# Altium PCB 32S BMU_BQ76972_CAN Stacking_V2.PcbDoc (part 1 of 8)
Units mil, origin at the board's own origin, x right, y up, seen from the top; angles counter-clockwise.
Board outline 7319.29 x 5216.54 mil, 4 copper layers (Top Layer, Layer 1, Layer 2, Bottom Layer), stack 73.068 mil thick; 811 components, 524 nets, 2320 pads, 2669 vias.
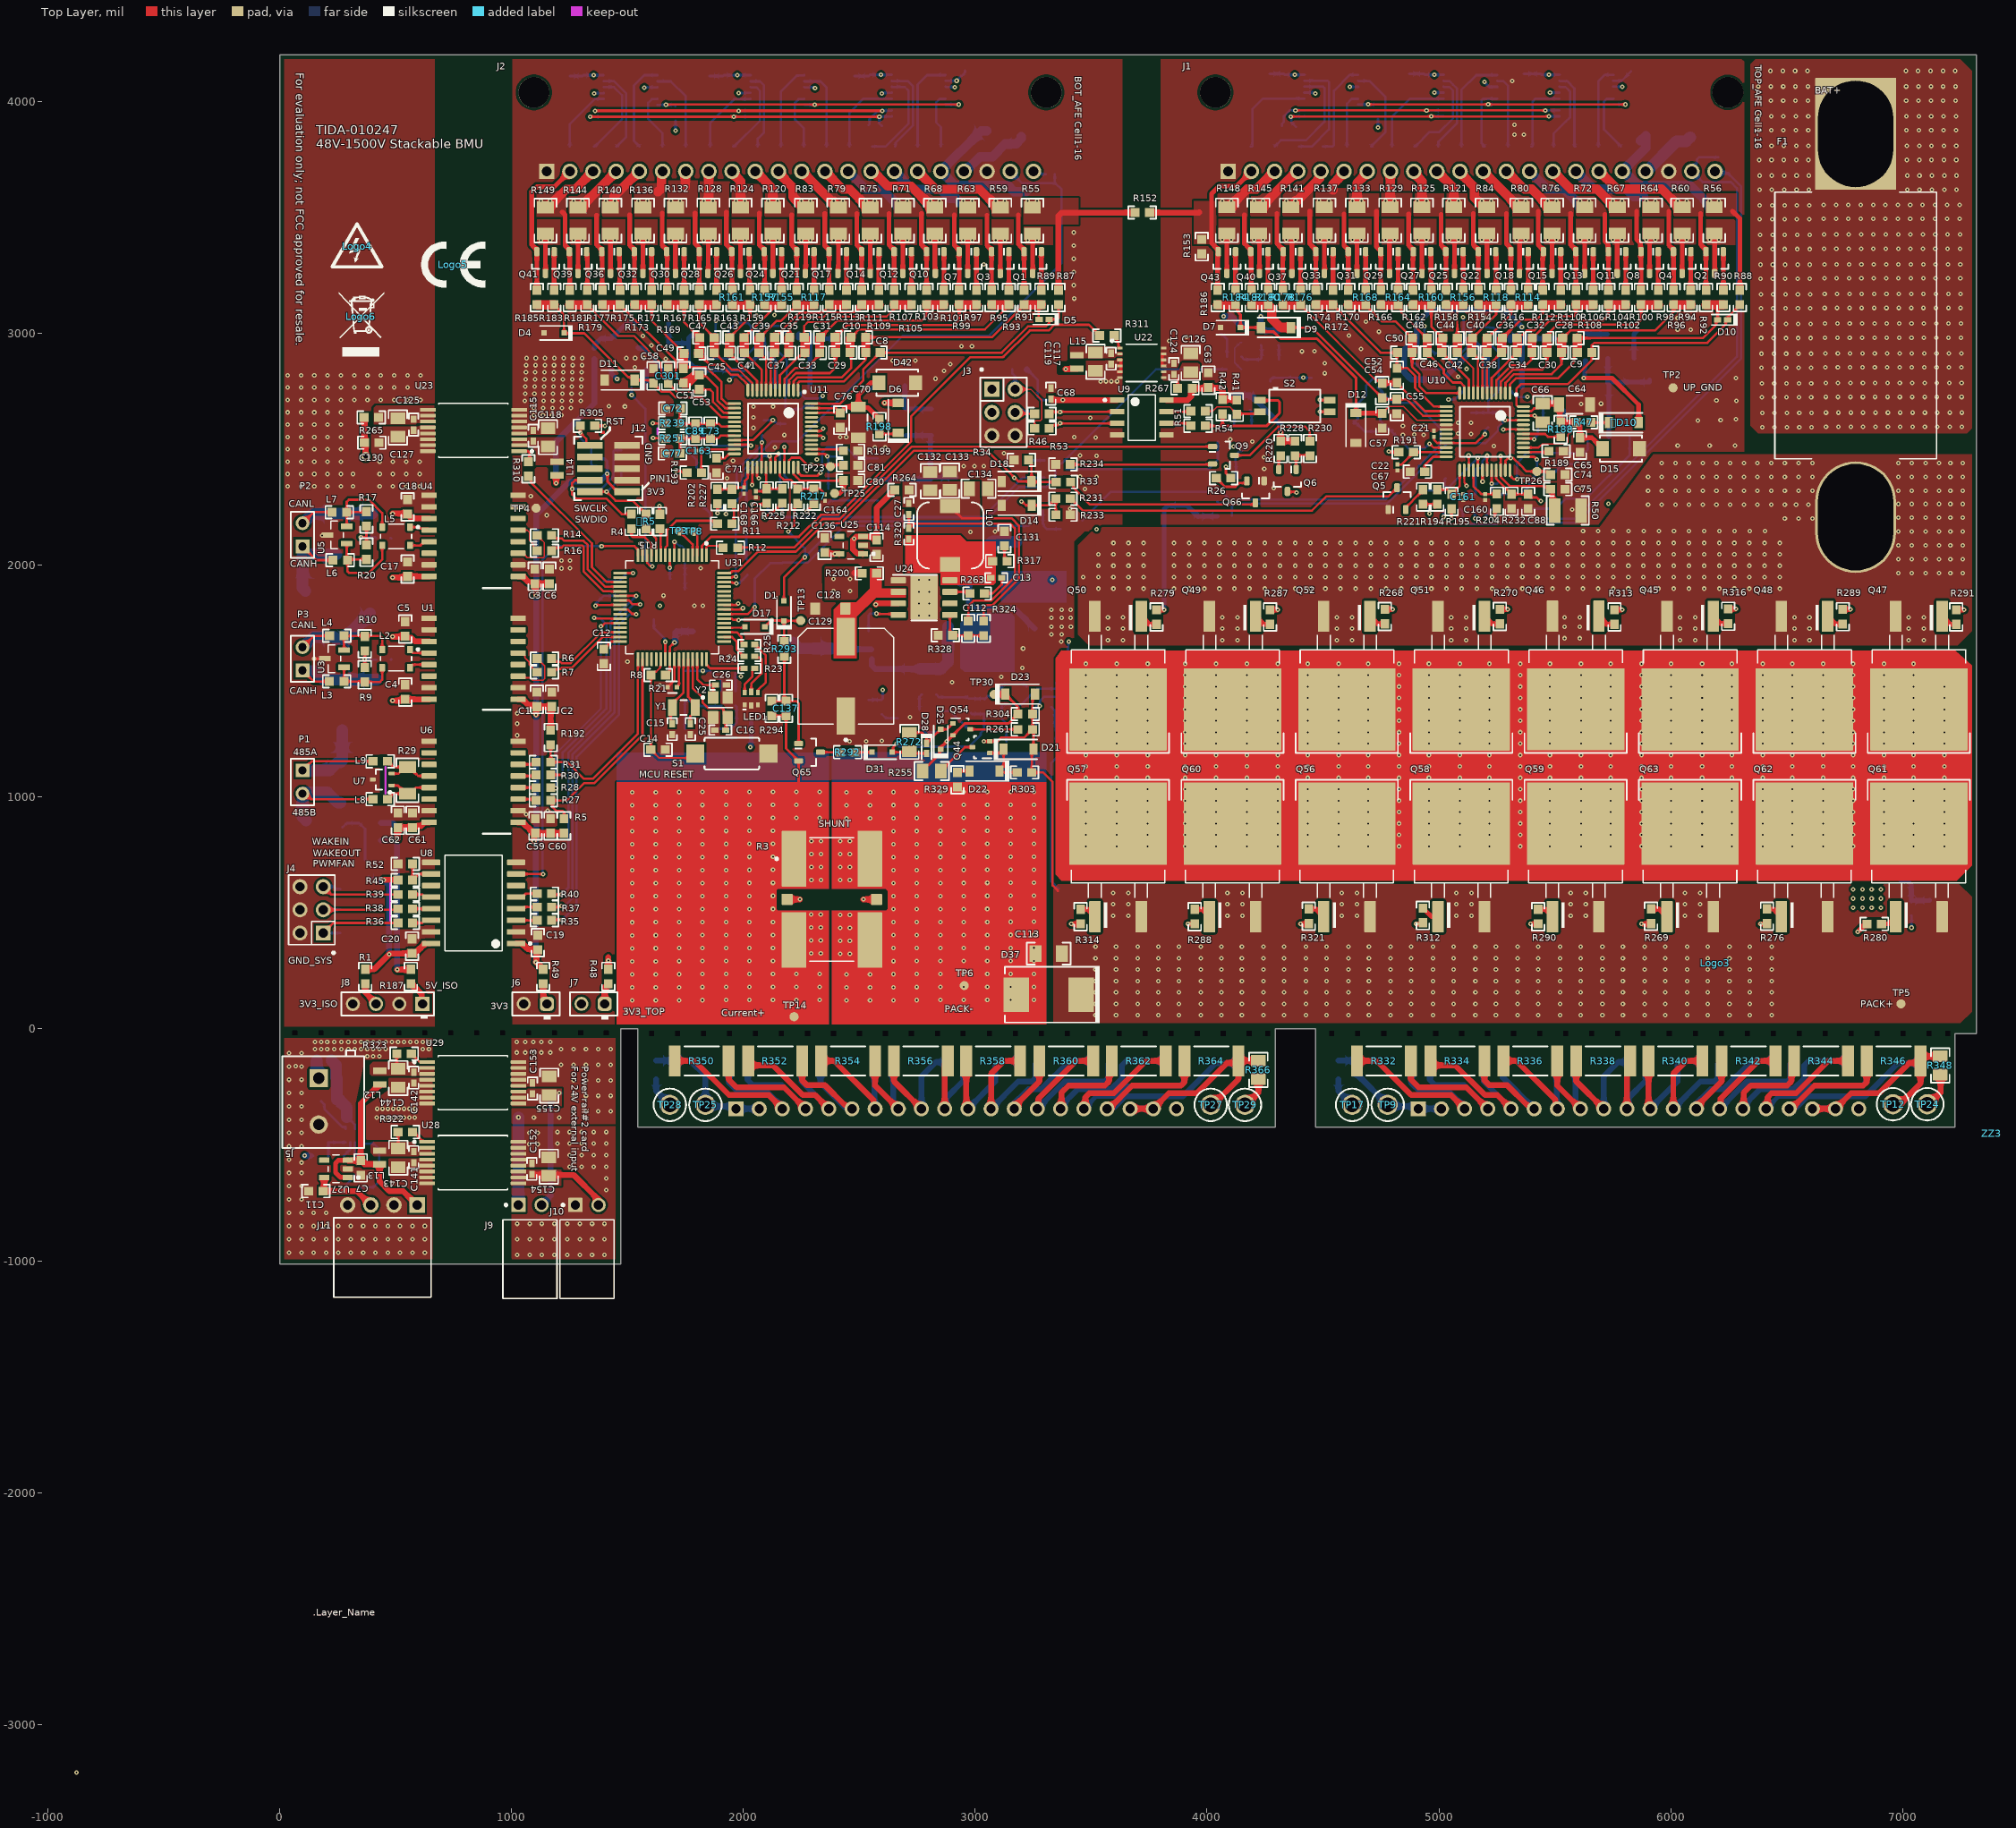
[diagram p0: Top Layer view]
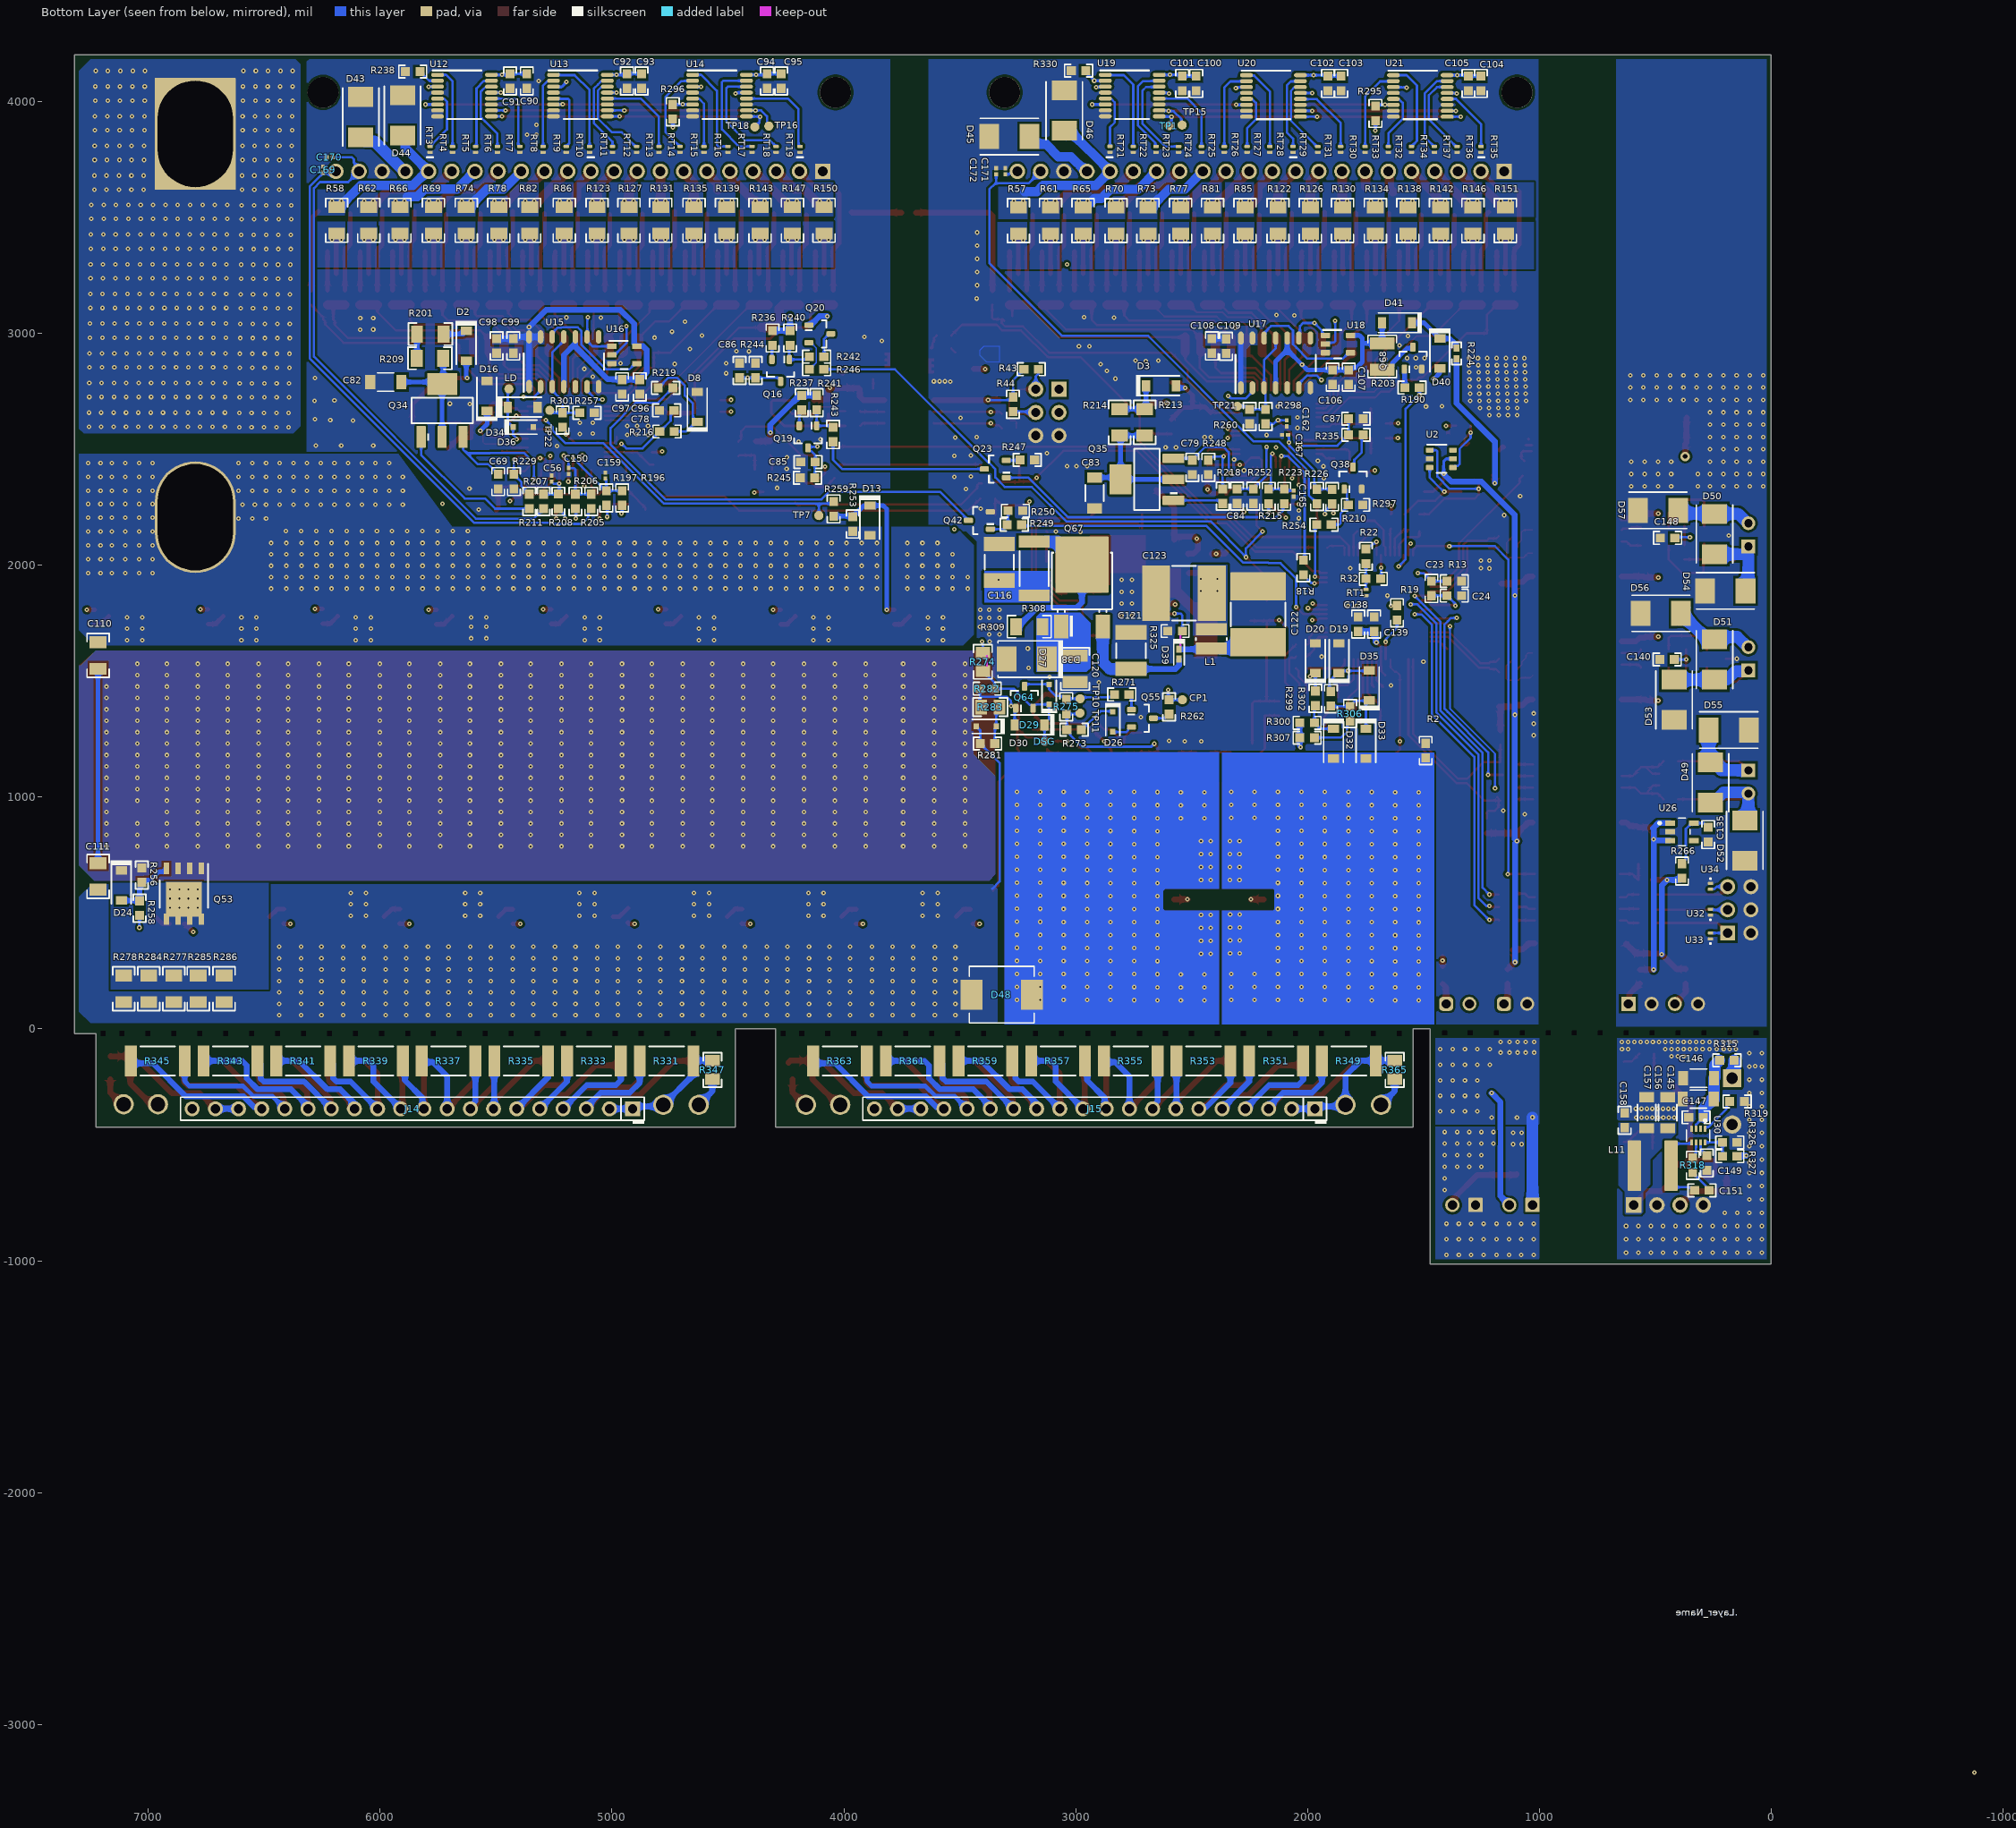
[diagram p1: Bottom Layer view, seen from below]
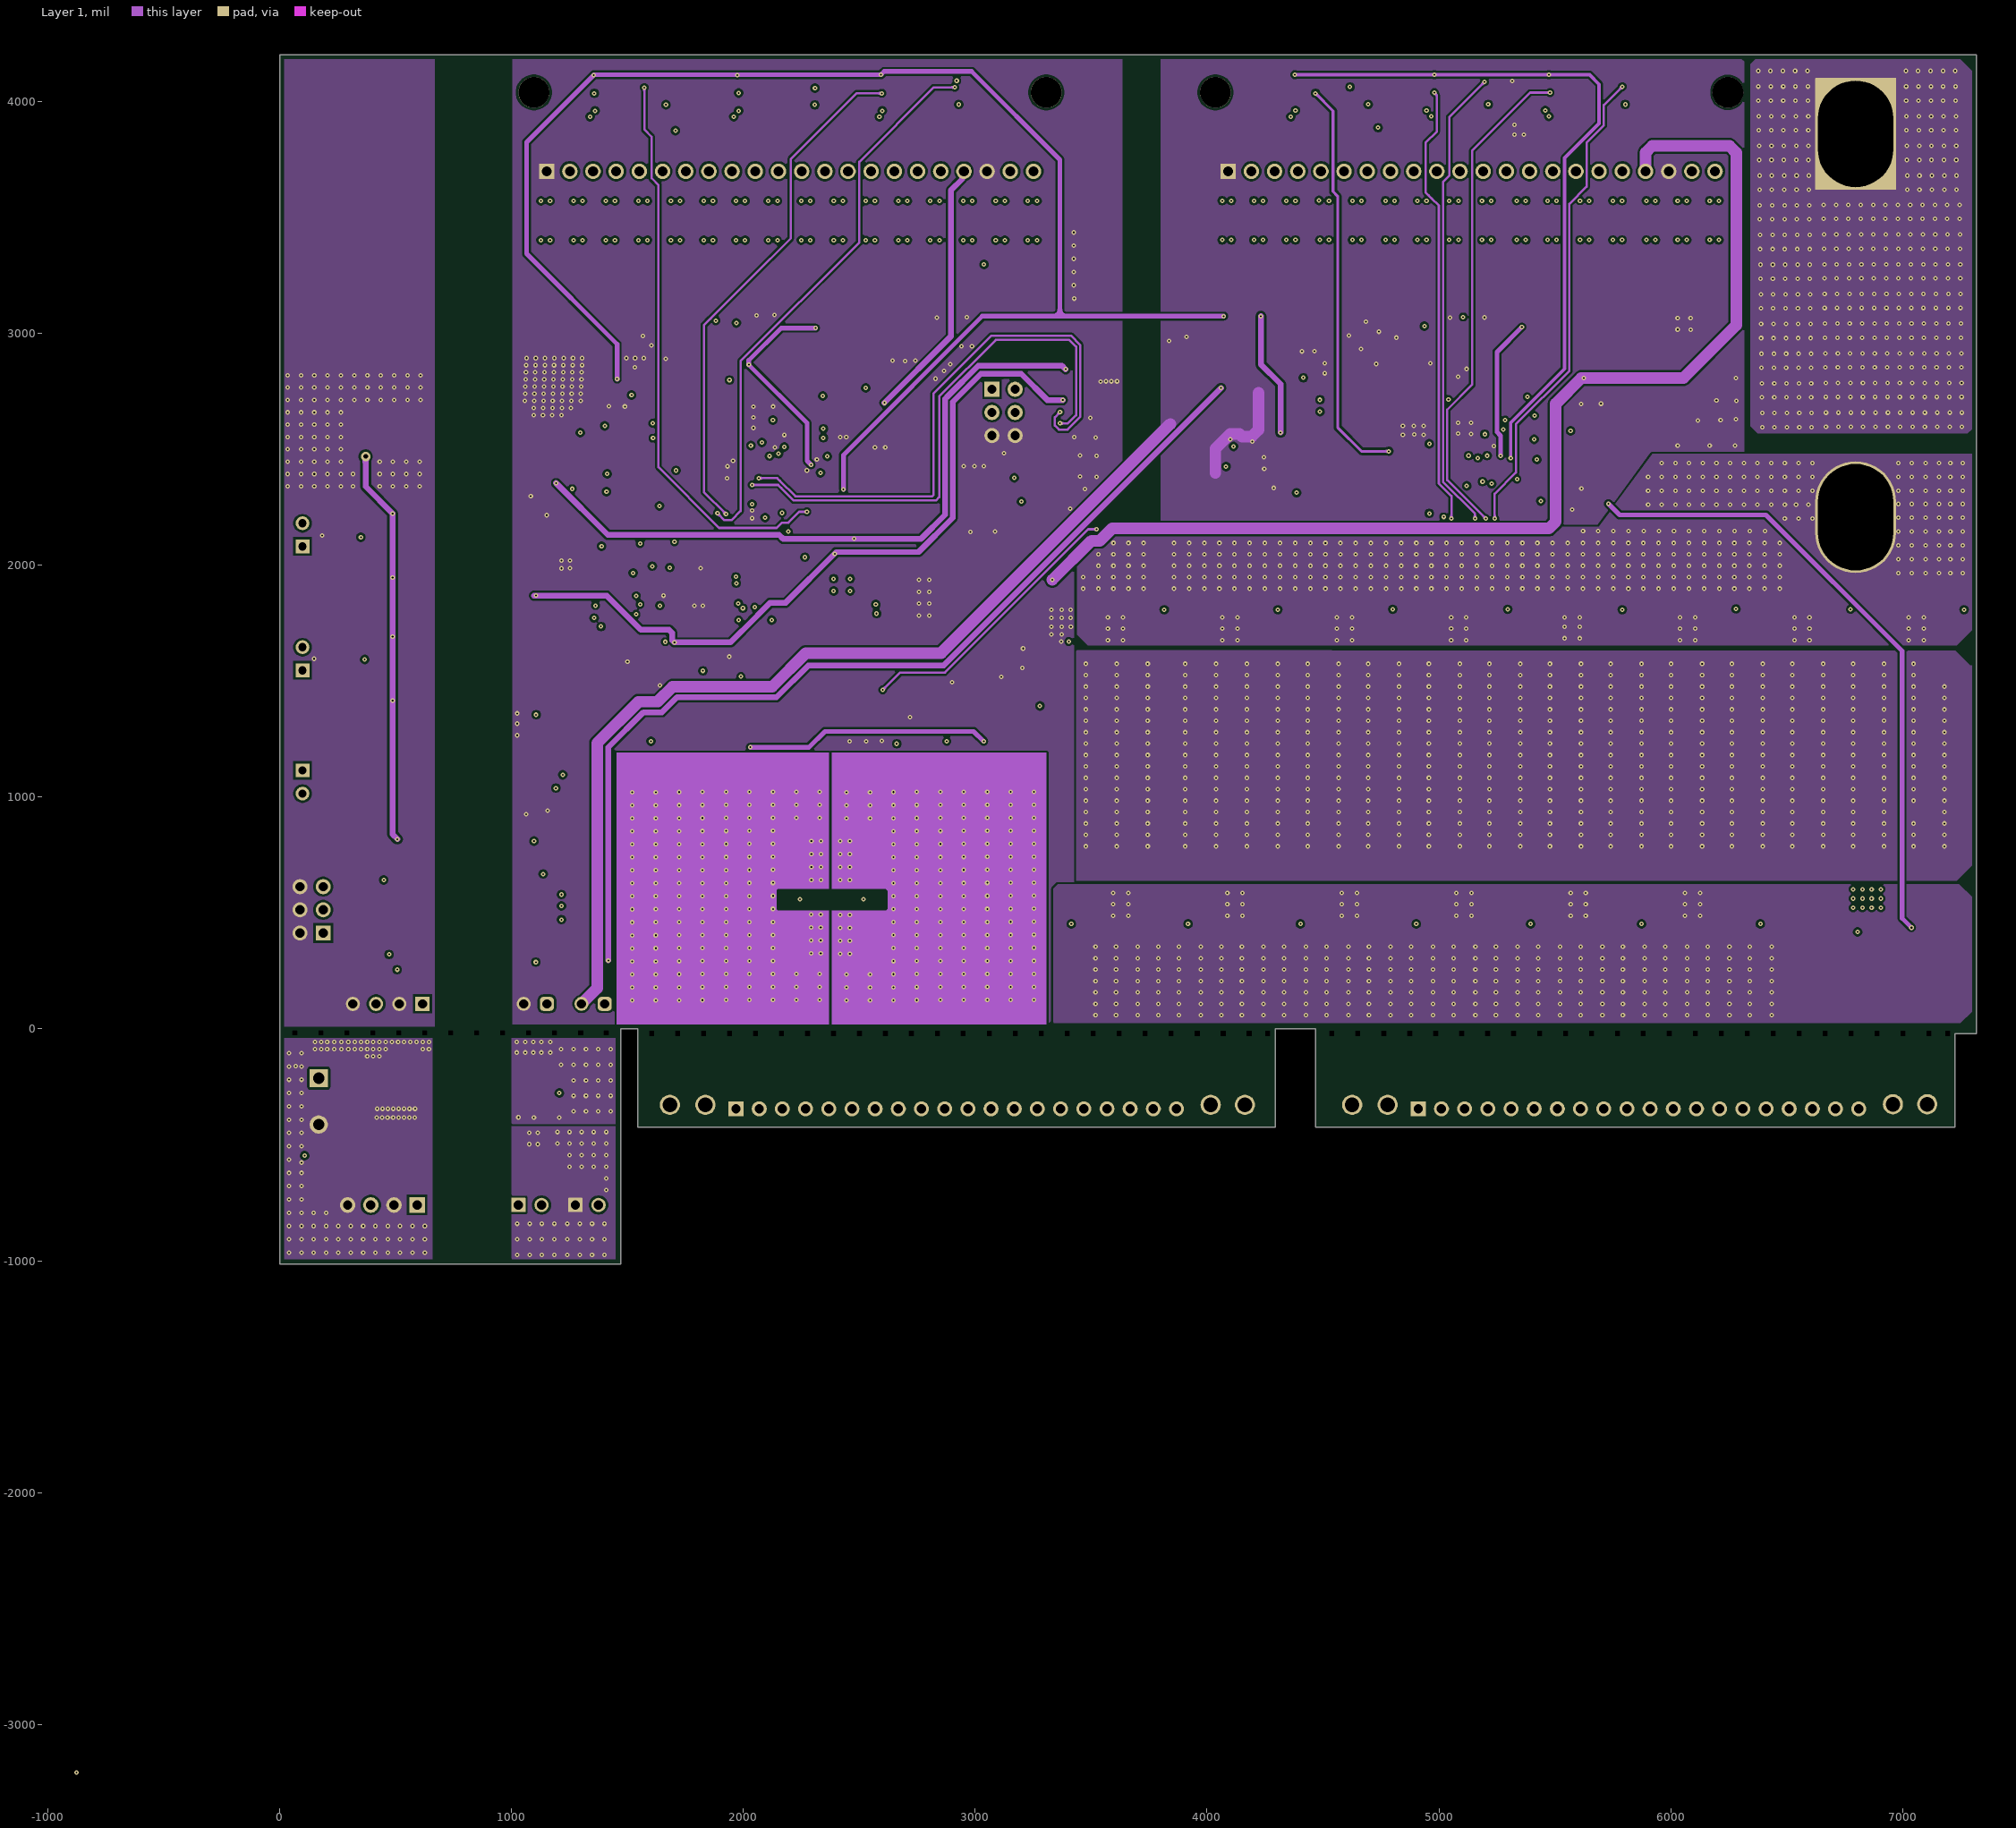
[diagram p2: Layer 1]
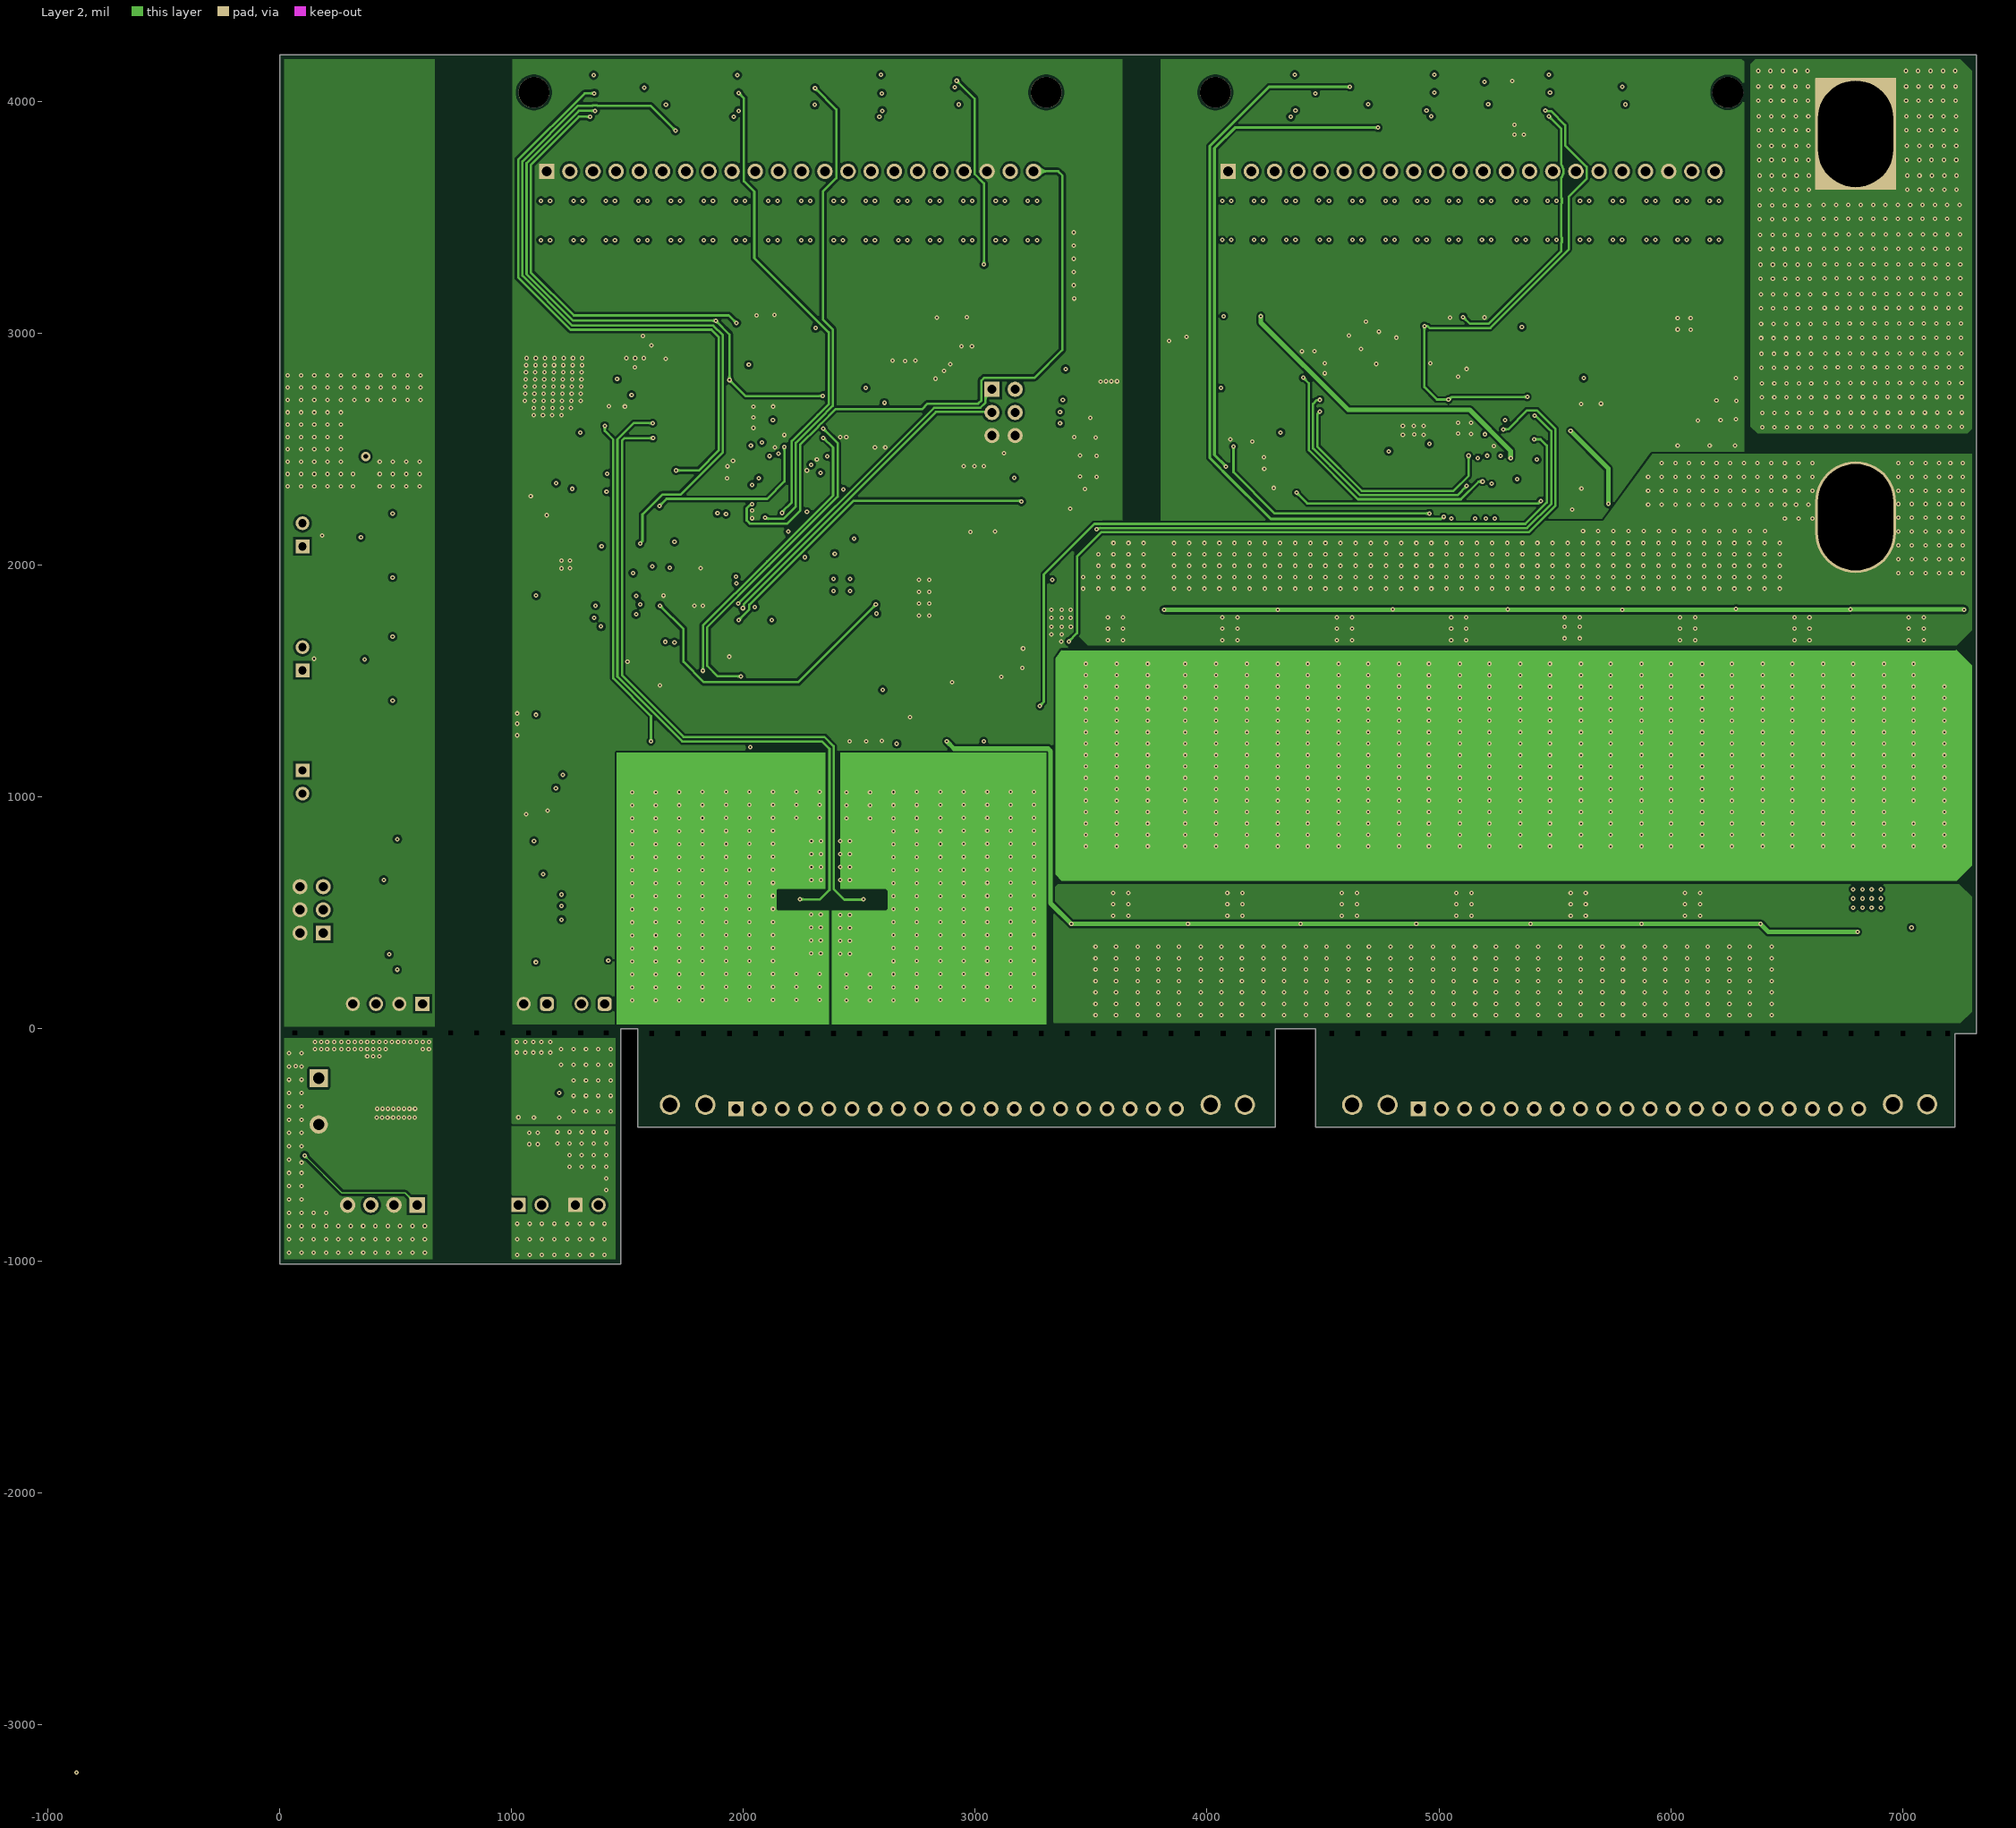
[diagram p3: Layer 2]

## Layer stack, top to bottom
Top Solder: solder mask 0.4, Solder Resist, Dk 3.5
Top Layer: signal copper 2.756
Dielectric 1: prepreg 2.8, PP-006, Dk 4.1
Layer 1: signal copper 1.378
Dielectric1: core 59.2, FR-4 High Tg, Dk 4.8
Layer 2: signal copper 1.378
Dielectric 2: prepreg 2.8, PP-006, Dk 4.1
Bottom Layer: signal copper 2.756
Bottom Solder: solder mask 0.4, Solder Resist, Dk 3.5

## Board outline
0,-1013.78 1470.69,-1013.78 1470.69,0 1545.28,0 1545.28,-423.54 4293.61,-423.54 4293.61,0 4468.5,0 4468.5,-423.54 7226.68,-423.54 7226.68,-19.68 7319.29,-19.68 7319.29,4202.76 0,4202.76

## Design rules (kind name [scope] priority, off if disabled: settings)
AcuteAngle [All] p1: minimum=4.50000000000000E+0001 checktracksonly=FALSE
AssemblyTestPointUsage [All] p1: valid=2
BoardOutlineClearance [Not InComponent('J1_2') AND  Not InComponent('J1_1')] p1: gap=0 ignorepadtopadclearanceinfootprint=FALSE except(20: Arc-OutlineEdge Arc-CavityEdge Arc-CutoutEdge Arc-SplitBarrior Arc-SplitContinuation Fill-OutlineEdge Fill-CavityEdge Fill-CutoutEdge Fill-SplitBarrior Fill-SplitContinuation Poly-OutlineEdge Poly-CavityEdge Poly-CutoutEdge Poly-SplitBarrior Poly-SplitContinuation Region-OutlineEdge Region-CavityEdge Region-CutoutEdge Region-SplitBarrior Region-SplitContinuation)
Clearance Clearance_BoardEdge_MountingHoles [OnCopper and InComponentClass('Mounting Holes') vs IsKeepOut] p1: gap=40 ignorepadtopadclearanceinfootprint=FALSE except(0: Arc-Hole Track-Hole SMDPad-Hole THPad-Hole Via-Hole Fill-Hole Poly-Hole Region-Hole Text-Hole)
Clearance Clearance_BoardEdge_Poly [OnCopper and InPoly vs IsKeepOut] p2: gap=20 ignorepadtopadclearanceinfootprint=FALSE except(0: Arc-Hole Track-Hole SMDPad-Hole THPad-Hole Via-Hole Fill-Hole Poly-Hole Region-Hole Text-Hole)
Clearance Clearance_BoardEdge [OnCopper and Not InComponentClass('Logo') and not InComponentClass('FiducialMark') and not InRegion(1000,500,4000,800) and Not IsKeepout vs IsKeepOut] p3: gap=5 ignorepadtopadclearanceinfootprint=FALSE except(0: Arc-Hole Track-Hole SMDPad-Hole THPad-Hole Via-Hole Fill-Hole Poly-Hole Region-Hole Text-Hole)
Clearance Clearance_Poly [InPolygon] p4: gap=10 ignorepadtopadclearanceinfootprint=FALSE except(0: Arc-Hole Track-Hole SMDPad-Hole THPad-Hole Via-Hole Fill-Hole Poly-Hole Region-Hole Text-Hole)
Clearance [All] p5: gap=8 ignorepadtopadclearanceinfootprint=FALSE except(0: Arc-Hole Track-Hole SMDPad-Hole THPad-Hole Via-Hole Fill-Hole Poly-Hole Region-Hole Text-Hole; 7: SMDPad-SMDPad)
ComponentClearance ComponentClearance_Logo [All] p1: gap=10 collisioncheckmode=3 verticalgap=10 showdistances=TRUE
ComponentClearance ComponentClearance_ScrewToNut [(HasFootprint('NY PMS 440 0025 PH')) vs (HasFootprint('Keystone_1902C'))] p2: gap=5 collisioncheckmode=3 verticalgap=10 showdistances=FALSE
ComponentClearance ComponentClearance_MountingHoles [InComponentClass('Mounting Holes')] p3: gap=10 collisioncheckmode=3 verticalgap=100000 showdistances=FALSE
ComponentClearance ComponentClearance_SmallPassives [HasFootprint('0201*') or HasFootprint('0402*') or HasFootprint('0508') or HasFootprint('0603*') or HasFootprint('0612') or HasFootprint('0805*') or HasFootprint('0815*') or HasFootprint('0830*') or HasFootprint('1206*') or HasFootprint('1210*') or HasFootprint('1808*') or HasFootprint('1812*') or HasFootprint('1825*') or HasFootprint('2010*') or HasFootprint('2220*') or HasFootprint('2225*') or HasFootprint('2512*') or HasFootprint('2728*') or HasFootprint('3518*') vs HasFootprint('0201*') or HasFootprint('0402*') or HasFootprint('0508') or HasFootprint('0603*') or HasFootprint('0612') or HasFootprint('0805*') or HasFootprint('0815*') or HasFootprint('0830*') or HasFootprint('1206*') or HasFootprint('1210*') or HasFootprint('1808*') or HasFootprint('1812*') or HasFootprint('1825*') or HasFootprint('2010*') or HasFootprint('2220*') or HasFootprint('2225*') or HasFootprint('2512*') or HasFootprint('2728*') or HasFootprint('3518*')] p4: gap=10 collisioncheckmode=3 verticalgap=10 showdistances=FALSE
ComponentClearance ComponentClearance_THtoSMT [IsThruComponent vs IsSMTComponent] p5: gap=10 collisioncheckmode=3 verticalgap=100000 showdistances=FALSE
ComponentClearance ComponentClearance_THtoTH [IsThruComponent vs IsThruComponent] p6: gap=10 collisioncheckmode=3 verticalgap=100000 showdistances=FALSE
ComponentClearance [All] p7: gap=10 collisioncheckmode=3 verticalgap=10 showdistances=FALSE
DiffPairsRouting [All] p1: maxlimit=100 minlimit=10 mostfreqgap=10 toplayer_minwidth=15 toplayer_maxwidth=15 toplayer_prefwidth=15 midlayer1_minwidth=15 midlayer1_maxwidth=15 midlayer1_prefwidth=15 midlayer2_minwidth=15 midlayer2_maxwidth=15 midlayer2_prefwidth=15 bottomlayer_minwidth=15 bottomlayer_maxwidth=15 bottomlayer_prefwidth=15 maxuncoupledlength=1000
FabricationTestPointUsage TestPointUsage [All] p1: valid=2 allowmultiple=FALSE
FabricationTestpoint Testpoint [All] p1: side=3 testpointundercomponent=TRUE minsize=40 maxsize=100 preferedsize=60 minholesize=0 maxholesize=40 preferedholesize=32 testpointgrid=1 allowsidetop=TRUE allowsidebottom=TRUE usegrid=TRUE gridtolerance=0.01
FanoutControl Fanout_LCC [IsLCC] p1: bgadir=Out bgaviamode=Centered fanoutstyle=Auto fanoutdirection=Alternating viagrid=1 // Fanout_LCC (Default Rule)
FanoutControl Fanout_BGA [IsBGA] p2: bgadir=Out bgaviamode=Centered fanoutstyle=Auto fanoutdirection=Alternating viagrid=1 // Fanout_BGA (Default Rule)
FanoutControl Fanout_Default [All] p4: bgadir=Out bgaviamode=Centered fanoutstyle=Auto fanoutdirection=Alternating viagrid=1 // Fanout_Default (Default Rule)
FanoutControl Fanout_Small [(CompPinCount < 5)] p5: bgadir=Out bgaviamode=Centered fanoutstyle=Auto fanoutdirection=OutThenIn viagrid=1 // Fanout_Small (Default Rule)
HoleSize [Not InComponent('F1')] p1: absolutevalues=TRUE maxlimit=251 minlimit=6 maxpercent=80.000 minpercent=20.000
MinimumAnnularRing [All] p1: minimumring=3
MinimumSolderMaskSliver MinimumSolderMaskSliver_Logo [InComponentClass('Logo') vs InComponentClass('Logo')] p1: minsoldermaskwidth=0.7
MinimumSolderMaskSliver [All] p2: minsoldermaskwidth=0
PlaneConnect [All] p1: planeconnectstyle=Direct reliefexpansion=10 reliefentries=4 reliefconductorwidth=10 reliefairgap=10
PolygonConnect [All] p1: connectstyle=Direct reliefconductorwidth=10 reliefentries=4 polygonreliefangle="90 Angle" airgapwidth=10
RoutingCorners [All] p1: cornerstyle=45-Degree minsetback=10 maxsetback=100
RoutingVias [All] p1: holewidth=16 width=34 viastyle="Through Hole" minholewidth=0 minwidth=0 maxholewidth=40 maxwidth=65
SMDToCorner [All] p1: distance=0
SilkToBoardRegionClearance [Not ((IsComment or IsDesignator) And (Hide <> 'False')) and not InRegion(1000,500,4000,800)] p1:
SilkToSilkClearance [All] p1: silktosilkclearance=0
SilkToSolderMaskClearance SilkscreenOverComponentPads [IsPad] p1: minsilkscreentomaskgap=0 clearancetoexposedcopper=TRUE
SolderMaskExpansion [All] p1: expansion=3 istentingtop=FALSE
Width [All] p1: maxlimit=100 minlimit=6 preferedwidth=10 checkconnectedcopper=TRUE
14 further rules are at their usual default settings.

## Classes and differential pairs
component class S8: J14 J15 R331 R332 R333 R334 R335 R336 R337 R338 R339 R340 R341 R342 R343 R344 R345 R346 R347 R348 R349 R350 R351 R352 R353 R354 R355 R356 R357 R358 R359 R360 R361 R362 R363 R364 R365 R366 TP9 TP12 TP17 TP24 TP25 TP27 TP28 TP29
component class U_EVM_Hardware: !PCB1 Logo3 Logo4 Logo5 Logo6 ZZ1 ZZ2 ZZ3
component class S6: C7 C11 C141 C142 C143 C144 C145 C146 C147 C149 C151 C152 C153 C154 C155 C156 C157 C158 J9 J10 J11 L11 L12 L13 R315 R318 R319 R322 R323 R326 R327 U27 U28 U29 U30
component class S5: C13 C27 C112 C114 C115 C116 C117 C118 C119 C120 C121 C122 C123 C124 C125 C126 C127 C128 C129 C130 C131 C132 C133 C134 C135 C136 D38 D39 J6 J7 J8 L1 L10 L14 L15 Q67 R1 R48 R49 R187 R200 R263 R264 R265 R266 R267 R308 R309 R310 R311 R317 R320 R324 R325 R328 U22 U23 U24 U25 U26
component class S4: C90 C91 C92 C93 C94 C95 C96 C97 C98 C99 C100 C101 C102 C103 C104 C105 C106 C107 C108 C109 R238 R257 R260 R295 R296 R298 R301 R330 RT3 RT4 RT5 RT6 RT7 RT8 RT9 RT10 RT11 RT12 RT13 RT14 RT15 RT16 RT17 RT18 RT19 RT21 RT22 RT23 RT24 RT25 RT26 RT27 RT28 RT29 RT30 RT31 RT32 RT33 RT34 RT35 RT36 RT37 TP1 TP15 TP16 TP18 TP21 TP22 TP23 TP25 TP26 U12 U13 U14 U15 U16 U17 U18 U19 U20 U21
component class S3: C1 C2 C3 C4 C5 C6 C12 C14 C15 C16 C17 C18 C19 C20 C23 C24 C25 C26 C59 C60 C61 C62 C63 C68 C138 C139 C140 C148 D17 D18 D49 D50 D51 D52 D53 D54 D55 D56 D57 J3 J12 L2 L3 L4 L5 L6 L7 L8 L9 LED1 Q66 R4 R5 R6 R7 R8 R9 R10 R11 R12 R13 R14 R15 R16 R17 R18 R19 R20 R21 R22 R23 R24 R25 R26 R27 R28 R29 R30 R31 R32 R33 R34 R35 R36 R37 R38 R39 R40 R41 R42 R43 R44 R45 R46 R51 R52 R53 R54 R192 R305 RT1 S1 S2 TP3 TP8 U1 U2 U3 U4 U5 U6 U7 U8 U9 U31 U32 U33 U34 Y1 Y2
component class S2: C110 C111 C113 C137 CP1 D13 D16 D19 D20 D21 D22 D23 D24 D25 D26 D27 D28 D29 D30 D31 D32 D33 D34 D35 D36 D37 D48 DSG F1 LD Q44 Q45 Q46 Q47 Q48 Q49 Q50 Q51 Q52 Q53 Q54 Q55 Q56 Q57 Q58 Q59 Q60 Q61 Q62 Q63 Q64 Q65 R253 R255 R256 R258 R259 R261 R262 R268 R269 R270 R271 R272 R273 R274 R275 R276 R277 R278 R279 R280 R281 R282 R283 R284 R285 R286 R287 R288 R289 R290 R291 R292 R293 R294 R299 R300 R302 R303 R304 R306 R307 R312 R313 R314 R316 R321 R329 TP5 TP6 TP7 TP10 TP11 TP13 TP14 TP30
component class S1: C8 C9 C10 C21 C22 C28 C29 C30 C31 C32 C33 C34 C35 C36 C37 C38 C39 C40 C41 C42 C43 C44 C45 C46 C47 C48 C49 C50 C51 C52 C53 C54 C55 C56 C57 C58 C64 C65 C66 C67 C69 C70 C71 C72 C73 C74 C75 C76 C77 C78 C79 C80 C81 C82 C83 C84 C85 C86 C87 C88 C89 C150 C159 C160 C161 C162 C163 C164 C165 C166 C167 C168 C301 D2 D3 D4 D5 D6 D7 D8 D9 D10 D11 D12 D14 D15 D40 D41 D42 Q1 Q2 Q3 Q4 Q5 Q6 Q7 Q8 Q9 Q10 Q11 Q12 Q13 Q14 Q15 Q16 Q17 Q18 Q19 Q20 Q21 Q22 Q23 Q24 Q25 Q26 Q27 Q28 Q29 Q30 Q31 Q32 Q33 Q34 Q35 Q36 Q37 Q38 Q39 Q40 Q41 Q42 Q43 Q68 R47 R50 R55 R56 R57 R58 R59 R60 R61 R62 R63 R64 R65 R66 R67 R68 R69 R70 R71 R72 R73 R74 R75 R76 R77 R78 R79 R80 R81 R82 R83 R84 R85 R86 R87 R88 R89 R90 R91 R92 R93 R94 R95 R96 R97 R98 R99 R100 R101 R102 R103 R104 R105 R106 R107 R108 R109 R110 R111 R112 R113 R114 R115 R116 R117 R118 R119 R120 R121 R122 R123 R124 R125 R126 R127 R128 R129 R130 R131 R132 R133 R134 R135 R136 R137 R138 R139 R140 R141 R142 R143 R144 R145 R146 R147 R148 R149 R150 R151 R152 R153 R154 R155 R156 R157 R158 R159 R160 R161 R162 R163 R164 R165 R166 R167 R168 R169 R170 R171 R172 R173 R174 R175 R176 R177 R178 R179 R180 R181 R182 R183 R184 R185 R186 R188 R189 R190 R191 R193 R194 R195 R196 R197 R198 R199 R201 R202 R203 R204 R205 R206 R207 R208 R209 R210 R211 R212 R213 R214 R215 R216 R217 R218 R219 R220 R221 R222 R223 R224 R225 R226 R227 R228 R229 R230 R231 R232 R233 R234 R235 R236 R237 R239 R240 R241 R242 R243 R244 R245 R246 R247 R248 R249 R250 R251 R252 R254 R297 TP2 TP4 U10 U11
component class "High Level Sheet": C169 C170 C171 C172 D1 D43 D44 D45 D46 J1 J2 J4 J5 P1 P2 P3 R2 R3

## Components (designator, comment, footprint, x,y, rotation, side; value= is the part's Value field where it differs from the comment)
D10 "BAT46W-7-F" SOD-123 5797.43,2615.29 r0 top value=100V (schematic designator D10)
R5 "CRCW0603100RFKEA" 0603 1580.52,2189.14 r270 top value=100 (schematic designator R5)
C1 "GRM188R61C104KA01D" 0603 1109.36,1421.63 r90 top value=0.1uF
C2 "CC0603MRX5R7BB105" 0603 1173.92,1421.63 r90 top value=1uF
C3 "EMK107BBJ106MA-T" 0603 1100.5,1952.08 r90 top value=0.1uF
C4 "GRM188R61C104KA01D" 0603 541.45,1453.12 r90 top value=0.1uF
C5 "GRM188R61C104KA01D" 0603 541.45,1725.45 r90 top value=0.1uF
C6 "EMK107BBJ106MA-T" 0603 1163.49,1952.08 r90 top value=1uF
C7 "GCM188R71C105KA64D" 0603 349.65,-599.42 r270 top value=1uF
C8 "GRM188R71H104KA93D" 0603 2558.95,2917.56 r180 top value=0.1uF
C9 "GRM188R71H104KA93D" 0603 5628.53,2917.56 r180 top value=0.1uF
C10 "GRM188R71H104KA93D" 0603 2496.13,2983.7 r180 top value=0.1uF
C11 "GRM188Z71C225KE43" 0603 156.29,-699.33 r180 top value=2.2uF
C12 "GCM188R71C474KA55D" 0603 1398.12,1606.97 r90 top value=0.47uF
C13 "GRM155R71H222KA01D" 0402 3090.77,1945.98 r180 top value=2200pF
C14 "C0603X103K1RACTU" 0603 1631.89,1204.72 r0 top value=0.01uF
C15 "GRM1555C1H220JA01D" 0402 1692.91,1293.31 r90 top value=22pF
C16 "GRM1555C1H220JA01D" 0402 1900.34,1289.37 r180 top value=22pF
C17 "GRM188R61C104KA01D" 0603 551.29,1983.58 r90 top value=0.1uF
C18 "GRM188R61C104KA01D" 0603 551.29,2252.08 r90 top value=0.1uF
C19 "GRM188R61C104KA01D" 0603 1113.26,372.42 r270 top value=0.1uF
C20 "GRM188R61C104KA01D" 0603 570.98,357.34 r270 top value=0.1uF
C21 "GRM033R71C471KA01D" 0201 4979.03,2566.69 r270 top value=470pF
C22 "GRM033R71C471KA01D" 0201 4821.61,2422.08 r90 top value=470pF
C23 "GCM188R71C105KA64J" 0603 1465.57,1900.22 r270 bottom value=1uF
C24 "C1608X5R1E105K080AC" 0603 1367.15,1868.72 r180 bottom value=1uF
C25 "GRM1555C1H220JA01D" 0402 1771.65,1293.31 r90 top value=22pF
C26 "GRM1555C1H220JA01D" 0402 1903,1483.48 r0 top value=22pF
C27 "GRM155R71H152KA01D" 0402 2713.67,2243.2 r270 top value=1500pF
C28 "GRM188R71H104KA93D" 0603 5564.8,2980.12 r180 top value=0.1uF
C29 "GRM188R71H104KA93D" 0603 2428.72,2917.56 r180 top value=0.1uF
C30 "GRM188R71H104KA93D" 0603 5497.53,2917.56 r180 top value=0.1uF
C31 "GRM188R71H104KA93D" 0603 2363.87,2983.7 r180 top value=0.1uF
C32 "GRM188R71H104KA93D" 0603 5434.34,2980.12 r180 top value=0.1uF
C33 "GRM188R71H104KA93D" 0603 2297.35,2916.58 r180 top value=0.1uF
C34 "GRM188R71H104KA93D" 0603 5369.58,2917.56 r180 top value=0.1uF
C35 "GRM188R71H104KA93D" 0603 2230.87,2983.7 r180 top value=0.1uF
C36 "GRM188R71H104KA93D" 0603 5305.4,2980.12 r180 top value=0.1uF
C37 "GRM188R71H104KA93D" 0603 2164.31,2916.58 r180 top value=0.1uF
C38 "GRM188R71H104KA93D" 0603 5239.1,2917.56 r180 top value=0.1uF
C39 "GRM188R71H104KA93D" 0603 2103.28,2983.7 r180 top value=0.1uF
C40 "GRM188R71H104KA93D" 0603 5176.34,2980.12 r180 top value=0.1uF
C41 "GRM188R71H104KA93D" 0603 2036.35,2916.58 r180 top value=0.1uF
C42 "GRM188R71H104KA93D" 0603 5110.57,2917.56 r180 top value=0.1uF
C43 "GRM188R71H104KA93D" 0603 1971.66,2982.71 r180 top value=0.1uF
C44 "GRM188R71H104KA93D" 0603 5048.34,2980.12 r180 top value=0.1uF
C45 "GRM188R71H104KA93D" 0603 1905.12,2916.58 r180 top value=0.1uF
C46 "GRM188R71H104KA93D" 0603 4981.08,2917.56 r180 top value=0.1uF
C47 "GRM188R71H104KA93D" 0603 1842.75,2982.71 r180 top value=0.1uF
C48 "GRM188R71H104KA93D" 0603 4917.86,2980.12 r180 top value=0.1uF
C49 "GRM188R71H104KA93D" 0603 1775.68,2914.05 r180 top value=0.1uF
C50 "GRM188R71H104KA93D" 0603 4853.11,2917.56 r180 top value=0.1uF
C51 "GRM188R71H104KA93D" 0603 1741.68,2817.49 r270 top value=0.1uF
C52 "GRM188R71H104KA93D" 0603 4819.11,2819.02 r270 top value=0.1uF
C53 "GRM188R71H104KA93D" 0603 1809.68,2789.76 r270 top value=0.1uF
C54 "GRM188R71H104KA93D" 0603 4755.41,2753.7 r270 top value=0.1uF
C55 "GRM188R71H104KA93D" 0603 4818.66,2684.8 r270 top value=0.1uF
C56 "GRM033R71C471KA01D" 0201 5260.04,2374.02 r270 bottom value=470pF
C57 "GRM188R71H104KA93D" 0603 4755.88,2623.39 r270 top value=0.1uF
C58 "GRM188R71H104KA93D" 0603 1612.01,2816.91 r90 top value=0.1uF
C59 "GRM188R61C104KA01D" 0603 1103.16,875.84 r90 top value=0.1uF
C60 "CC0603MRX5R7BB105" 0603 1168.79,875.84 r90 top value=1uF
C61 "GRM188R61C104KA01D" 0603 572.94,900.16 r90 top value=0.1uF
C62 "CC0603MRX5R7BB105" 0603 509.95,900.16 r90 top value=1uF
C63 "GRM188R61C104KA01D" 0603 4005.34,2798.84 r270 top value=0.1uF
C64 "GRM31CR72A225KA73L" 1206_190 5584.81,2692.55 r180 top value=2.2uF
C65 "GRM1885C2A101JA01D" 0603 5608.8,2518.5 r90 top value=100pF
C66 "GRM21BR71E225KA73L" 0805_HV 5447.66,2656.93 r90 top value=2.2uF
C67 "EMK107BB7225MA-T" 0603 4907.49,2403.83 r180 top value=2.2uF
C68 "GRM188R71H104KA93D" 0402 3326.46,2740.48 r90 top value=0.1uF
C69 "GRM188R71H223KA01D" 0603 5491.16,2361.02 r270 bottom value=0.022uF
C70 "GRM31CR72A225KA73L" 1206_190 2496.13,2616.78 r90 top value=2.2uF
C71 "EMK107BB7225MA-T" 0603 1884.49,2430.37 r270 top value=2.2uF
C72 "GRM188R61C104KA01D" 0603 1696.43,2676.89 r180 top value=0.1uF
C73 "GRM188R61C104KA01D" 0603 1858.4,2578.9 r90 top value=0.1uF
C74 "GCM188R71C105KA64D" 0603 5512.81,2391.1 r180 top value=1uF
C75 "GCM188R71C105KA64D" 0603 5512.81,2328.18 r180 top value=1uF
C76 "GRM1885C2A101JA01D" 0603 2417.72,2625.74 r90 top value=100pF
C77 "GRM188R61C104KA01D" 0603 1694.51,2482.58 r0 top value=0.1uF
C78 "GRM1885C2A101JA01D" 0603 4764.07,2668.29 r0 bottom value=100pF
C79 "GRM188R71H223KA01D" 0603 2497.16,2422.39 r270 bottom value=0.022uF
C80 "GCM188R71C105KA64D" 0603 2462.72,2365.6 r180 top value=1uF
C81 "GCM188R71C105KA64D" 0603 2462.72,2431.41 r180 top value=1uF
C82 "C3216X7R2A105K160AA" 1206_180 5976.06,2790.2 r0 bottom value=1uF
C83 "C3216X7R2A105K160AA" 1206_180 2918.76,2311.81 r270 bottom value=1uF
C84 "GRM1885C2A101JA01D" 0603 2303.73,2298.04 r270 bottom value=100pF
C85 "GRM1885C1H470JA01D" 0603 4154.69,2445.66 r0 bottom value=47pF
C86 "GRM1885C1H470JA01D" 0603 4449.97,2840.55 r90 bottom value=47pF
C87 "GRM1885C2A101JA01D" 0603 1791.34,2631.89 r180 bottom value=100pF
C88 "GRM1885C1H470JA01D" 0603 5385.36,2275.57 r270 top value=47pF
C89 "GRM1885C2A101JA01D" 0603 1793.1,2578.9 r270 top value=100pF
C90 "GRM188R61C104KA01D" 0603 5367.5,4088.78 r270 bottom value=0.1uF
C91 "CC0603MRX5R7BB105" 0603 5440.22,4088.78 r270 bottom value=1uF
C92 "GRM188R61C104KA01D" 0603 4935.82,4088.78 r270 bottom value=0.1uF
C93 "CC0603MRX5R7BB105" 0603 4872.45,4088.78 r270 bottom value=1uF
C94 "GRM188R61C104KA01D" 0603 4331.47,4088.78 r270 bottom value=0.1uF
C95 "CC0603MRX5R7BB105" 0603 4270.53,4088.78 r270 bottom value=1uF
C96 "CC0603MRX5R7BB105" 0603 4880.54,2769.77 r270 bottom value=1uF
C97 "GRM188R61C104KA01D" 0603 4956.51,2769.77 r270 bottom value=0.1uF
C98 "CC0603MRX5R7BB105" 0603 5497.53,2946.11 r270 bottom value=1uF
C99 "GRM188R61C104KA01D" 0603 5425.95,2946.11 r270 bottom value=0.1uF
C100 "GRM188R61C104KA01D" 0603 2479.96,4078.63 r270 bottom value=0.1uF
C101 "CC0603MRX5R7BB105" 0603 2540.79,4078.63 r270 bottom value=1uF
C102 "GRM188R61C104KA01D" 0603 1912.21,4078.63 r270 bottom value=0.1uF
C103 "CC0603MRX5R7BB105" 0603 1855.12,4078.63 r270 bottom value=1uF
C104 "GRM188R61C104KA01D" 0603 1252.2,4078.63 r270 bottom value=0.1uF
C105 "CC0603MRX5R7BB105" 0603 1306.34,4078.63 r270 bottom value=1uF
C106 "CC0603MRX5R7BB105" 0603 1891.89,2811.41 r270 bottom value=1uF
C107 "GRM188R61C104KA01D" 0603 1822.48,2811.41 r270 bottom value=0.1uF
C108 "CC0603MRX5R7BB105" 0603 2412.63,2946.11 r270 bottom value=1uF
C109 "GRM188R61C104KA01D" 0603 2351.43,2945.12 r270 bottom value=0.1uF
C110 "C1206C104K2RACTU" 1206 7217.17,1610.79 r90 bottom value=0.1uF
C111 "C1206C104K2RACTU" 1206 7217.17,658 r90 bottom value=0.1uF
C112 "GRM1885C2A101JA01D" 0603 2969.89,1728.11 r270 top value=100pF
C113 "C1206C104K2RACTU" 1206 3316.93,324.8 r180 top value=0.1uF
C114 "GCM188R71C105KA64D" 0603 2574.66,2077.72 r270 top value=1uF
C115 "GCM155R71H222KA37D" 0402 1093.57,2558.98 r90 top value=2200pF
C116 "18122C105KAT2A" 1812_280 3329.21,2013.23 r90 bottom value=1uF
C117 "GCM155R71H222KA37D" 0402 3586.48,2891.43 r270 top value=2200pF
C118 "GRM21BZ71A226ME15L" 0805_HV 1157.37,2552.39 r90 top value=22uF
C119 "GRM21BZ71A226ME15L" 0805_HV 3519.03,2877.95 r270 top value=22uF
C120 "C1210C683J2RACTU" 1210 3002.58,1553.13 r270 bottom value=0.068uF
C121 "18122C105KAT2A" 1812_280 2761.2,1631.87 r90 bottom value=1uF
C122 "2220Y2000225KXTWS2" 2220_450 2213.39,1788.35 r90 bottom value=1uF
C123 "2220Y2000225KXTWS2" 2220_450 2532.93,1879.55 r0 bottom value=1uF
C124 "GCM155R71H222KA37D" 0402 3857.08,2847.17 r90 top value=2200pF
C125 "GCM155R71H222KA37D" 0402 577.64,2606.74 r270 top value=2200pF
C126 "GRM21BZ71A226ME15L" 0805_HV 3929.58,2873.03 r90 top value=22uF
C127 "GRM21BZ71A226ME15L" 0805_HV 509.91,2594.54 r270 top value=22uF
C128 "C1206C104K2RAC7800" FP-CGA5H2X8R2A104K115AA_1206-MFG 2374.68,1813.22 r180 top
C129 "EEV-EB2C100Q" FP-EEV-EB2C100Q_RADIAL-MFG 2441.76,1520.84 r90 top value=10µF
C130 "GCM188R71C105KA64D" 0603 396.95,2528.95 r0 top value=1uF
C131 "GRM1885C1H560JA01D" 0603 3126.2,2115.53 r90 top value=56pF
C132 "GRM21BR71C475KA73L" 0805_HV 2805.73,2362.85 r90 top value=4.7uF
C133 "GRM21BR71C475KA73L" 0805_HV 2890.83,2365.27 r90 top value=4.7uF
C134 "GRM21BR71C475KA73L" 0805_HV 3014.55,2330.49 r0 top value=4.7uF
C135 "GRM188Z71C225KE43" 0603 271.54,838.49 r270 bottom value=2.2uF
C136 "GRM188Z71C225KE43" 0603 2350.74,2086.68 r90 top value=2.2uF
C137 "GRM1885C2A101JA01D" 0603 2184.22,1382.74 r270 top value=100pF
C138 "EMK107BBJ106MA-T" 0603 1781.5,1746.06 r90 bottom value=10uF
C139 "GRM188R61C104KA01D" 0603 1712.6,1746.06 r90 bottom value=0.1uF
C140 "GRM188R71H104KA93D" 0603 448.7,1593.56 r180 bottom value=0.1uF
C141 "GCM155R71H222KA37D" 0402 578.2,-553.07 r270 top value=2200pF
C142 "GCM155R71H222KA37D" 0402 578.2,-209.81 r270 top value=2200pF
C143 "GRM21BZ71A226ME15L" 0805_HV 511.33,-555.74 r270 top value=22uF
C144 "GRM21BZ71A226ME15L" 0805_HV 511.12,-212.07 r270 top value=22uF
C145 "CGA5L1X7R1H106K160AC" 1206_190 314.43,-302.62 r0 bottom value=10uF
C146 "CGA5L1X7R1H106K160AC" 1206_190 313.32,-212.46 r0 bottom value=10uF
C147 "C0603C104K5RACAUTO" 0603 324.27,-381.36 r0 bottom value=0.1uF
C148 "GRM188R71H104KA93D" 0603 446.89,2118.3 r180 bottom value=0.1uF
C149 "GRM188R71C333KA01D" 0603 277.4,-578.21 r270 bottom value=0.033uF
C150 "GRM033R71C471KA01D" 0201 5187.31,2407.02 r90 bottom value=470pF
C151 "C0603C104K5RACAUTO" 0603 299.1,-696.32 r0 bottom value=0.1uF
C152 "GCM155R71H222KA37D" 0402 1087.65,-603.77 r90 top value=2200pF
C153 "GCM155R71H222KA37D" 0402 1090.38,-256.57 r90 top value=2200pF
C154 "GRM21BZ71A226ME15L" 0805_HV 1161.08,-593.94 r90 top value=22uF
C155 "GRM21BZ71A226ME15L" 0805_HV 1162.44,-244.94 r90 top value=22uF
C156 "C3216X5R1V226M160AC" 1206_180 446.29,-361.68 r90 bottom value=22uF
C157 "C3216X5R1V226M160AC" 1206_180 537.32,-361.68 r90 bottom value=22uF
C158 "C0603C104K5RACAUTO" 0603 631.98,-393.87 r90 bottom value=0.1uF
C159 "GRM033R71C471KA01D" 0201 5028.8,2387.01 r270 bottom value=470pF
C160 "GRM033R71C471KA01D" 0201 5199.8,2294.38 r90 top value=470pF
C161 "GRM033R71C471KA01D" 0201 5104.84,2294.5 r90 top value=470pF
C162 "GRM033R71C471KA01D" 0201 2089.71,2612.35 r90 bottom value=470pF
C163 "GRM033R71C471KA01D" 0201 1809.66,2493.85 r0 top value=470pF
C164 "GRM033R71C471KA01D" 0201 2352.2,2291.52 r90 top value=470pF
C165 "GRM033R71C471KA01D" 0201 2059.72,2309.31 r90 bottom value=470pF
C166 "GRM033R71C471KA01D" 0201 2054.22,2306.58 r90 top value=470pF
C167 "GRM033R71C471KA01D" 0201 2096.73,2562.49 r180 bottom value=470pF
C168 "GRM033R71C471KA01D" 0201 2003.15,2322.33 r90 top value=470pF
C169 "GRM033R71C471KA01D" 0201 6246.39,3706.68 r90 bottom value=470pF
C170 "GRM033R71C471KA01D" 0201 6217.84,3759.84 r0 bottom value=470pF
C171 "GRM033R71C471KA01D" 0201 3303.71,3699.61 r90 bottom value=470pF
C172 "GRM033R71C471KA01D" 0201 3342.99,3699.61 r90 bottom value=470pF
C301 "GRM188R71H104KA93D" 0603 1676.32,2816.91 r90 top value=0.1uF
CP1 "" TP_SM_1MM 2539.76,1419.82 r90 bottom
D1 "PMEG2020EJ,115" SOD-323F 2175.2,1803.64 r90 top value=20V
D2 "BAT46W-7-F" SOD-123 5628.49,2946.42 r270 bottom value=100V
D3 "BAT46W-7-F" SOD-123 2632.11,2774.41 r180 bottom value=100V
D4 "BAT42WS-7-F" SOD-323 1183.42,3002.18 r180 top value=30V
D5 "BAT41KFILM" SOD-523 3297.38,3061.16 r180 top value=100V
D6 "BAT46W-7-F" SOD-123 2668.05,2635.58 r90 top value=100V
D7 "BAT42WS-7-F" SOD-323 4100.79,3025.59 r180 top value=30V
D8 "BAT42WS-7-F" SOD-123 4632.37,2683.29 r90 bottom value=30V
D9 "BAT46W-7-F" SOD-123 4297.64,3025.59 r180 top value=100V
D10 "BAT41KFILM" SOD-523 6223.95,3059.12 r180 top value=100V
D11 "MMSZ4685T1G" SOD-123 1465.97,2798.78 r180 top value=3.6V
D12 "MMSZ4685T1G" SOD-123 4642.13,2592.52 r270 top value=3.6V
D13 "MMSZ5246B-7-F" SOD-123 3887.8,2193.35 r270 bottom value=16V
D14 "MMSZ4685T1G" SOD-123 3179,2258.7 r180 top value=3.6V
D15 "SMAJ60CA" SMA_Bi 5785.92,2503.25 r0 top value=60V
D16 "MMSZ5267BT1G" SOD-123 5540.14,2730.32 r90 bottom value=75V
D17 "DB2J20900L" SOD-323F 2049.48,1734.91 r180 top value=20V
D18 "MMSZ4685T1G" SOD-123 3178.62,2361.85 r180 top value=3.6V
D19 "MMSZ5267BT1G" SOD-123 1864.34,1599.12 r90 bottom value=75V
D20 "MMSZ5267BT1G" SOD-123 1966.1,1599.12 r90 bottom value=75V
D21 "MMSZ5246B-7-F" SOD-123 3186.85,1206.33 r0 top value=16V
D22 "BAT46W-7-F" SOD-123 3040.14,1112.44 r180 top value=100V
D23 "MMSZ5246B-7-F" SOD-123 3194.3,1444.14 r0 top value=16V
D24 "MMSZ5246B-7-F" SOD-123 7116.51,618.97 r270 bottom value=16V
D25 "BZT52C5V1S-7-F" SOD-323 2851.13,1249.12 r90 top value=5.1V
D26 "BAT46WJ,115" SOD-323F 2840.03,1325.51 r270 bottom value=100V
D27 "NC" SOD-323F 3114.53,1443.11 r90 bottom value=100V
D28 "BAS516,115" SOD-523 2790.56,1210.43 r270 top value=100V
D29 "MMSZ5246B-7-F" SOD-123 3198.68,1312.02 r0 bottom value=16V
D30 "BAT46WJ,115" SOD-323F 3385.83,1305.29 r0 bottom value=100V
D31 "BAT46WJ,115" SOD-323F 2598.43,1193.85 r0 top value=100V
D32 "BAT46W-7-F" SOD-123 1888.2,1230.32 r270 bottom value=100V
D33 "BAT46W-7-F" SOD-123 1748.2,1230.32 r270 bottom value=100V
D34 "MMSZ5267BT1G" SOD-123 5385.14,2682.13 r180 bottom value=75V
D35 "BAT46W-7-F" SOD-123 1733.37,1482.34 r90 bottom value=100V
D36 "BAT46WJ,115" SOD-323F 5383.5,2596.31 r180 bottom value=100V
D37 "ES5GC" SMC 3316.93,147.64 r180 top value=400V
D38 "SMBJ5376B-TP" SMB 3210.47,1595.22 r0 bottom value=91V
D39 "BAS516,115" SOD-523 2554.43,1616.87 r270 bottom value=100V
D40 "B0520LW-7-F" SOD-123 1429.35,2913.62 r270 bottom value=20V
D41 "B0520LW-7-F" SOD-123 1614.01,3046 r0 bottom value=20V
D42 "SMAJ60CA" SMA_Bi 2663.9,2787.97 r0 top value=60V
D43 "SMBJ60CA" SMB-Bi 6083.73,3933.65 r270 bottom value=60V
D44 "SMBJ60CA" SMB-Bi 5903.88,3940.56 r270 bottom value=60V
D45 "SMBJ60CA" SMB-Bi 3286.06,3849.61 r180 bottom value=60V
D46 "SMBJ60CA" SMB-Bi 3049.1,3961.42 r270 bottom value=60V
D48 "SMDJ120CA" FP-SMDJ54CA_DO-214AB-MFG 3319.2,147.64 r180 bottom
D49 "SMBJ7.0CA" SMB-Bi 261.69,1062.99 r270 bottom value=7V
D50 "SMBJ7.0CA" SMB-Bi 244.74,2134.86 r90 bottom value=7V
D51 "SMBJ7.0CA" SMB-Bi 244.74,1593.56 r90 bottom value=7V
D52 "SMBJ7.0CA" SMB-Bi 113.79,812.9 r90 bottom value=7V
D53 "SMBJ7.0CA" SMB-Bi 419.01,1419.82 r90 bottom value=7V
D54 "SMBJ7.0CA" SMB-Bi 197.7,1889.76 r180 bottom value=7V
D55 "SMBJ7.0CA" SMB-Bi 182.95,1289.37 r0 bottom value=7V
D56 "SMBJ7.0CA" SMB-Bi 475.73,1792.65 r180 bottom value=7V
D57 "SMBJ7.0CA" SMB-Bi 488.58,2236.55 r180 bottom value=7V
DSG "" TP_SM_1MM 3134.21,1240.51 r90 bottom
F1 "PF-MB1-150" FP-PF-MB1-150_BT_FUSE_56MM0_17MM4-MFG 6797.64,3034.31 r270 top
J1 "705550056" FP-705550056_HDR22-MFG 5141.28,3941.54 r180 top
J2 "705550056" FP-705550056_HDR22-MFG 2201.43,3941.54 r180 top
J3 "TSW-103-07-G-D" TSW-103-07-G-D 3122.23,2659.26 r270 top
J4 "TSW-103-07-G-D" TSW-103-07-G-D 137.74,513.68 r90 top
J5 "ED120/2DS" On-Shore_ED120_2DS 168.21,-312.46 r270 top
J6 "TSW-102-08-G-S" Samtec_TSW-102-08-x-S 1102.36,108.05 r180 top
J7 "TSW-102-08-G-S" Samtec_TSW-102-08-x-S 1351.89,108.05 r180 top
J8 "PBC04SAAN" Sullins_xxC04SAAN 465.84,108.05 r180 top
J9 "PPTC021LGBN-RC" FP-PPTC021LGBN-RC_CONN_HDR2-MFG 1079.42,-989.79 r0 top
J10 "PPTC021LGBN-RC" FP-PPTC021LGBN-RC_CONN_HDR2-MFG 1325.48,-989.79 r0 top
J11 "PPPC041LGBN-RC" SULLINS_PPPC041LGBN-RC 442.89,-976.01 r0 top
J12 "FTSH-105-01-L-DV-K" Samtec_FTSH-105-01-x-DV-K 1417.32,2417.61 r180 top
J14 "613020143121" TSW-120-07-G-S 5861.13,-344.36 r0 bottom
J15 "613020143121" TSW-120-07-G-S 2918.36,-344.36 r0 bottom
L1 "74438335010" WE-MAPI_3015 2414.57,1682.52 r90 bottom value=1uH
L2 "SRF3225TAC-510Y" FP-SRF3225TAC-510Y_SMT4-MFG 502.08,1597.49 r180 top
L3 "74279265" 0603 245.7,1499.07 r180 top value="600 ohm"
L4 "74279265" 0603 246.17,1695.92 r180 top value="600 ohm"
L5 "SRF3225TAC-510Y" FP-SRF3225TAC-510Y_SMT4-MFG 502.08,2125.08 r180 top
L6 "74279265" 0603 260.96,2022.4 r180 top value="600 ohm"
L7 "74279265" 0603 257.51,2229.09 r180 top value="600 ohm"
L8 "74279265" 0603 433.18,991.17 r180 top value="600 ohm"
L9 "74279265" 0603 433.18,1154.58 r180 top value="600 ohm"
L10 "744777168" WE-PD_7345 2890.83,2129.89 r90 top value=68uH
L11 "74439346100" WE-XHMI_6060 510.93,-589.87 r0 bottom value=10uH
L12 "74479275222" WE-PMCI_0805_L2W1.25H1 431.7,-210.23 r90 top
L13 "74479275222" WE-PMCI_0805_L2W1.25H1 430.68,-554.13 r90 top
L14 "74479275222" WE-PMCI_0805_L2W1.25H1 1195.82,2417.61 r90 top
L15 "74479275222" WE-PMCI_0805_L2W1.25H1 3439.22,2877.3 r90 top
LD "" TP_SM_1MM 5444.69,2760.9 r90 bottom
LED1 "19-337/R6GHBHC-A01/2T" 19-337_RGB 2034.17,1424.6 r90 top value=Rgb
Logo3 "FCC disclaimer" FCC_disclaimer 6190.95,285.43 r0 top
Logo4 "DANGER HIGH VOLTAGE" IEC_HighVoltage_Small 333.65,3375.34 r0 top
Logo5 "CE Mark" CE_Mark_5mm 748.03,3297.24 r0 top
Logo6 "WEEE logo" WEEE_Minimum 350.28,3073.68 r0 top
P1 "Header 2" HDR1X2 98.53,1115.38 r270 top
P2 "Header 2" HDR1X2 98.53,2081.46 r90 top
P3 "Header 2" HDR1X2 98.53,1546.71 r90 top
Q1 "BSR14" SOT-23 3248.17,3305.91 r270 top value="40 V"
Q2 "BSR14" SOT-23 6189.54,3305.91 r270 top value="40 V"
Q3 "BSR14" SOT-23 3108.06,3305.91 r270 top value="40 V"
Q4 "BSR14" SOT-23 6049.27,3305.91 r270 top value="40 V"
Q5 "MMBTA56LT1G" SOT-23 4819.29,2287.4 r90 top value="80 V"
Q6 "MMBTA56LT1G" SOT-23 4346.85,2366.14 r270 top value="80 V"
Q7 "BSR14" SOT-23 2967.95,3305.91 r270 top value="40 V"
Q8 "BSR14" SOT-23 5909.01,3305.91 r270 top value="40 V"
Q9 "MMBTA05LT1G" SOT-23 4071.26,2474.41 r0 top value="60 V"
Q10 "BSR14" SOT-23 2827.84,3305.91 r270 top value="40 V"
Q11 "BSR14" SOT-23 5768.75,3305.91 r270 top value="40 V"
Q12 "BSR14" SOT-23 2687.73,3305.91 r270 top value="40 V"
Q13 "BSR14" SOT-23 5628.49,3305.91 r270 top value="40 V"
Q14 "BSR14" SOT-23 2547.63,3305.91 r270 top value="40 V"
Q15 "BSR14" SOT-23 5488.22,3305.91 r270 top value="40 V"
Q16 "MMBTA56LT1G" SOT-23 4272.8,2840.55 r270 bottom value="80 V"
Q17 "BSR14" SOT-23 2407.52,3305.91 r270 top value="40 V"
Q18 "BSR14" SOT-23 5347.96,3305.91 r270 top value="40 V"
Q19 "MMBTA56LT1G" SOT-23 4154.69,2554.27 r270 bottom value="80 V"
Q20 "MMBTA05LT1G" SOT-23 4103.33,2998.03 r180 bottom value="60 V"
Q21 "BSR14" SOT-23 2267.41,3305.91 r270 top value="40 V"
Q22 "BSR14" SOT-23 5207.7,3305.91 r270 top value="40 V"
Q23 "MMBTA05LT1G" SOT-23 3346.46,2415.35 r0 bottom value="60 V"
Q24 "BSR14" SOT-23 2127.3,3305.91 r270 top value="40 V"
Q25 "BSR14" SOT-23 5067.44,3305.91 r270 top value="40 V"
Q26 "BSR14" SOT-23 1987.19,3305.91 r270 top value="40 V"
Q27 "BSR14" SOT-23 4927.17,3305.91 r270 top value="40 V"
Q28 "BSR14" SOT-23 1847.09,3305.91 r270 top value="40 V"
Q29 "BSR14" SOT-23 4786.91,3305.91 r270 top value="40 V"
Q30 "BSR14" SOT-23 1706.98,3305.91 r270 top value="40 V"
Q31 "BSR14" SOT-23 4646.65,3305.91 r270 top value="40 V"
Q32 "BSR14" SOT-23 1566.87,3305.91 r270 top value="40 V"
Q33 "BSR14" SOT-23 4506.39,3305.91 r270 top value="40 V"
Q34 "FZT493TA" SOT-223 5732.79,2667.71 r90 bottom value="100 V"
Q35 "FZT493TA" SOT-223 2692.38,2370.87 r0 bottom value="100 V"
Q36 "BSR14" SOT-23 1426.76,3305.91 r270 top value="40 V"
Q37 "BSR14" SOT-23 4366.12,3305.91 r270 top value="40 V"
Q38 "BC846B,215" SOT-23 1803.89,2375.98 r90 bottom value="65 V"
Q39 "BSR14" SOT-23 1286.65,3305.91 r270 top value="40 V"
Q40 "BSR14" SOT-23 4225.86,3305.91 r270 top value="40 V"
Q41 "BSR14" SOT-23 1146.54,3305.91 r270 top value="40 V"
Q42 "BC846B,215" SOT-23 3415.35,2193.35 r0 bottom value="65 V"
Q43 "BSR14" SOT-23 4085.6,3305.91 r270 top value="40 V"
Q44 "2N7002W-7-F" SOT-323 3025.62,1215.66 r180 top value=60V
Q45 "IPB068N20NM6ATMA1" DDPAK 6083.53,1534.02 r270 top value=200V
Q46 "IPB068N20NM6ATMA1" DDPAK 5590.07,1534.21 r270 top value=200V
Q47 "IPB068N20NM6ATMA1" DDPAK 7070.45,1534.02 r270 top value=200V
Q48 "IPB068N20NM6ATMA1" DDPAK 6576.99,1534.02 r270 top value=200V
Q49 "IPB068N20NM6ATMA1" DDPAK 4109.69,1534.02 r270 top value=200V
Q50 "IPB068N20NM6ATMA1" DDPAK 3616.24,1534.02 r270 top value=200V
Q51 "IPB068N20NM6ATMA1" DDPAK 5096.61,1534.02 r270 top value=200V
Q52 "IPB068N20NM6ATMA1" DDPAK 4603.15,1534.02 r270 top value=200V
Q53 "SI7439DP-T1-E3" PowerPAK_SO-8 6846.85,582.32 r270 bottom value=-150V
Q54 "DMG1013UW-7" SOT-323 2941.19,1292.43 r0 top value=-20V
Q55 "FMMT495TA" SOT-23 2712.11,1340.29 r180 bottom value="150 V"
Q56 "IPB068N20NM6ATMA1" DDPAK 4603.15,730.39 r90 top value=200V
Q57 "IPB068N20NM6ATMA1" DDPAK 3616.24,730.39 r90 top value=200V
Q58 "IPB068N20NM6ATMA1" DDPAK 5096.61,730.39 r90 top value=200V
Q59 "IPB068N20NM6ATMA1" DDPAK 5590.07,730.39 r90 top value=200V
Q60 "IPB068N20NM6ATMA1" DDPAK 4109.69,730.39 r90 top value=200V
Q61 "IPB068N20NM6ATMA1" DDPAK 7070.45,730.39 r90 top value=200V
Q62 "IPB068N20NM6ATMA1" DDPAK 6576.99,730.39 r90 top value=200V
Q63 "IPB068N20NM6ATMA1" DDPAK 6083.53,730.39 r90 top value=200V
Q64 "SI2325DS-T1-E3" SOT-23 3220.88,1430.97 r90 bottom value=-150V
Q65 "CPH3461-TL-W" SOT-23 2285.44,1193.85 r0 top value=100V
Q66 "MMBTA56LT1G" SOT-23 4209.06,2316.93 r270 top value="80 V"
Q67 "ZXTN4004KTC" DPAK 2972.88,1869.1 r90 bottom value="150 V"
Q68 "MMBTA05LT1G" SOT-23 1545.12,2893.7 r90 bottom value="60 V"
R1 "RC0603JR-070RL" 0603 368.86,226.16 r270 top value=0
R2 "CRCW06030000Z0EA" 0603 1490.63,1200.79 r270 bottom value=0
R3 "SEWF3951FL300PT" FP-SEWF3951FL300PT_3951-MFG 2381.89,558.8 r0 top value=300µ
R4 "CRCW0603100RFKEA" 0603 1517.43,2189.32 r270 top value=100
R5 "CRCW060310K0FKEA" 0603 1226.55,875.84 r270 top value=10.0k
R6 "CRCW0603100RFKEA" 0603 1141.84,1597.49 r180 top value=100
R7 "CRCW0603100RFKEA" 0603 1141.84,1538.44 r180 top value=100
R8 "CRCW060347K0FKEA" 0603 1632.9,1526.2 r0 top value=47.0k
R9 "RC0603FR-0760R4L" 0603 367.07,1527.77 r270 top value=60.4
R10 "RC0603FR-0760R4L" 0603 367.07,1661.82 r270 top value=60.4
R11 "CRCW0603100RFKEA" 0603 1919.6,2179.71 r180 top value=100
R12 "CRCW0603100RFKEA" 0603 1944.07,2075.76 r180 top value=100
R13 "CRCW04020000Z0ED" 0603 1367.15,1931.72 r0 bottom value=0
R14 "CRCW0603100RFKEA" 0603 1141.84,2128.99 r180 top value=100
R15 "CRCW0603100RFKEA" 0603 1640.28,2189 r270 top value=100
R16 "CRCW0603100RFKEA" 0603 1141.84,2062.52 r180 top value=100
R17 "RC0603FR-0760R4L" 0603 374.12,2056.54 r270 top value=60.4
R18 "CRCW0603100RFKEA" 0603 2017.58,1990.25 r270 bottom value=100
R19 "CRCW0603100RFKEA" 0603 1614.17,1795.28 r270 bottom value=100
R20 "RC0603FR-0760R4L" 0603 374.12,2200.46 r270 top value=60.4
R21 "ERA-2AEB104X" FP-ERA-2AEB104X_0402-MFG 1693.6,1474.47 r180 top
R22 "CRCW0603100RFKEA" 0603 1747.87,2038.72 r90 bottom value=100
R23 "CRCW0402220RJNED" 0402 2026.18,1555.4 r0 top value=220
R24 "CRCW0402330RJNED" 0402 2025.86,1606.97 r0 top value=330
R25 "CRCW0402330RJNED" 0402 2026.18,1658.5 r0 top value=330
R26 "CRCW060326K1FKEA" 0603 4071.26,2375.98 r0 top value=26.1k
R27 "CRCW0603100RFKEA" 0603 1137.29,985.78 r180 top value=100
R28 "CRCW060310K0FKEA" 0603 1137.29,1040.97 r180 top value=10.0k
R29 "RC0603FR-07120RL" 1206 551.29,1072.46 r270 top value=120
R30 "CRCW060310K0FKEA" 0603 1137.29,1096.16 r180 top value=10.0k
R31 "CRCW0603100RFKEA" 0603 1137.29,1151.34 r180 top value=100
R32 "RT0603BRD0710KL" 0603 1716.38,1941.99 r180 bottom value=10.0k
R33 "CRCW0603200KFKEA" 0603 3380.28,2359.59 r0 top value=200k
R34 "RC0603FR-0733KL" 0603 3198.82,2454.72 r0 top value=33.0k
R35 "CRCW0603100RFKEA" 0603 1141.84,468.59 r180 top value=100
R36 "CRCW0603100RFKEA" 0603 541.45,457.22 r180 top value=100
R37 "CRCW0603100RFKEA" 0603 1141.84,526.18 r180 top value=100
R38 "CRCW0603100RFKEA" 0603 541.45,518.59 r180 top value=100
R39 "CRCW0603100RFKEA" 0603 541.45,579.89 r0 top value=100
R40 "CRCW0603100RFKEA" 0603 1141.84,583.71 r0 top value=100
R41 "RC0603FR-074K7L" 0603 4128.32,2681.61 r90 top value=4.70k
R42 "RC0603FR-074K7L" 0603 4066.99,2683.99 r90 top value=4.70k
R43 "RC0603FR-074K7L" 0603 3191.75,2845.89 r0 bottom value=4.70k
R44 "RC0603FR-074K7L" 0603 3270.36,2694.41 r90 bottom value=4.70k
R45 "CRCW060310K0FKEA" 0603 541.45,642.77 r180 top value=10.0k
R46 "CRCW0603100RFKEA" 0603 3287.54,2653.49 r0 top value=100
R47 "CRCW0603100RFKEA" 0603 5624,2616.93 r180 top value=100
R48 "RC0603JR-070RL" 0603 1417.32,226.16 r270 top value=0
R49 "RC0603JR-070RL" 0603 1136.57,226.16 r270 top value=0
R50 "RC1210FR-07220RL" 1210 5556.4,2236.23 r180 top value=220
R51 "CRCW0603100RFKEA" 0603 3961.08,2664.85 r0 top value=100
R52 "CRCW060310K0FKEA" 0603 541.45,711.67 r0 top value=10.0k
R53 "CRCW0603100RFKEA" 0603 3287.54,2591.03 r0 top value=100
R54 "CRCW0603100RFKEA" 0603 3961.08,2601.72 r0 top value=100
R55 "CRCW120680R6FKEA" 1206 3246.72,3487.01 r270 top value=80.6
R56 "CRCW120680R6FKEA" 1206 6187.94,3487.99 r270 top value=80.6
R57 "CRCW120680R6FKEA" 1206 3246.72,3487.01 r270 bottom value=80.6
R58 "CRCW120680R6FKEA" 1206 6187.94,3487.99 r270 bottom value=80.6
R59 "CRCW120680R6FKEA" 1206 3108.06,3487.01 r270 top value=80.6
R60 "CRCW120680R6FKEA" 1206 6049.27,3487.99 r270 top value=80.6
R61 "CRCW120680R6FKEA" 1206 3108.06,3487.01 r270 bottom value=80.6
R62 "CRCW120680R6FKEA" 1206 6049.27,3487.99 r270 bottom value=80.6
R63 "CRCW120680R6FKEA" 1206 2967.95,3487.01 r270 top value=80.6
R64 "CRCW120680R6FKEA" 1206 5914.71,3487.99 r270 top value=80.6
R65 "CRCW120680R6FKEA" 1206 2967.95,3487.01 r270 bottom value=80.6
R66 "CRCW120680R6FKEA" 1206 5914.71,3487.99 r270 bottom value=80.6
R67 "CRCW120680R6FKEA" 1206 5770.47,3487.99 r270 top value=80.6
R68 "CRCW120680R6FKEA" 1206 2825.89,3487.01 r270 top value=80.6
R69 "CRCW120680R6FKEA" 1206 5770.47,3487.99 r270 bottom value=80.6
R70 "CRCW120680R6FKEA" 1206 2825.89,3487.01 r270 bottom value=80.6
R71 "CRCW120680R6FKEA" 1206 2687.97,3487.01 r270 top value=80.6
R72 "CRCW120680R6FKEA" 1206 5628.49,3487.99 r270 top value=80.6
R73 "CRCW120680R6FKEA" 1206 2687.97,3487.01 r270 bottom value=80.6
R74 "CRCW120680R6FKEA" 1206 5628.49,3487.99 r270 bottom value=80.6
R75 "CRCW120680R6FKEA" 1206 2547.64,3487.01 r270 top value=80.6
R76 "CRCW120680R6FKEA" 1206 5488.22,3487.99 r270 top value=80.6
R77 "CRCW120680R6FKEA" 1206 2547.64,3487.01 r270 bottom value=80.6
R78 "CRCW120680R6FKEA" 1206 5488.22,3487.99 r270 bottom value=80.6
R79 "CRCW120680R6FKEA" 1206 2409.49,3487.01 r270 top value=80.6
R80 "CRCW120680R6FKEA" 1206 5355.26,3487.99 r270 top value=80.6
R81 "CRCW120680R6FKEA" 1206 2409.49,3487.01 r270 bottom value=80.6
R82 "CRCW120680R6FKEA" 1206 5355.26,3487.99 r270 bottom value=80.6
R83 "CRCW120680R6FKEA" 1206 2269.38,3487.01 r270 top value=80.6
R84 "CRCW120680R6FKEA" 1206 5205.73,3487.99 r270 top value=80.6
R85 "CRCW120680R6FKEA" 1206 2269.38,3487.01 r270 bottom value=80.6
R86 "CRCW120680R6FKEA" 1206 5205.73,3487.99 r270 bottom value=80.6
R87 "CRCW060320R0FKEA" 0603 3359.26,3155.31 r270 top value=20.0
R88 "CRCW060320R0FKEA" 0603 6298.25,3155.31 r270 top value=20.0
R89 "CRCW0603300RJNEA" 0603 3285.57,3155.31 r270 top value=300
R90 "CRCW0603300RJNEA" 0603 6226.94,3155.31 r270 top value=300
R91 "CRCW0603100RFKEA" 0603 3211.28,3155.31 r270 top value=100
R92 "CRCW0603100RFKEA" 0603 6152.51,3155.31 r270 top value=100
R93 "CRCW0603300RJNEA" 0603 3145.46,3155.31 r270 top value=300
R94 "CRCW0603300RJNEA" 0603 6086.67,3155.31 r270 top value=300
R95 "CRCW0603100RFKEA" 0603 3070.66,3155.31 r270 top value=100
R96 "CRCW0603100RFKEA" 0603 6012.51,3155.31 r270 top value=100
R97 "CRCW0603300RJNEA" 0603 3005.35,3155.31 r270 top value=300
R98 "CRCW0603300RJNEA" 0603 5946.41,3155.31 r270 top value=300
R99 "CRCW0603100RFKEA" 0603 2930.55,3155.31 r270 top value=100
R100 "CRCW0603100RFKEA" 0603 5871.61,3155.31 r270 top value=100
R101 "CRCW0603300RJNEA" 0603 2865.03,3155.31 r270 top value=300
R102 "CRCW0603300RJNEA" 0603 5805.9,3155.31 r270 top value=300
R103 "CRCW0603100RFKEA" 0603 2790.44,3155.31 r270 top value=100
R104 "CRCW0603100RFKEA" 0603 5731.35,3155.31 r270 top value=100
R105 "CRCW0603300RJNEA" 0603 2725.14,3155.31 r270 top value=300
R106 "CRCW0603300RJNEA" 0603 5665.89,3155.31 r270 top value=300
R107 "CRCW0603100RFKEA" 0603 2650.33,3155.31 r270 top value=100
R108 "CRCW0603100RFKEA" 0603 5591.08,3155.31 r270 top value=100
R109 "CRCW0603300RJNEA" 0603 2585.03,3155.31 r270 top value=300
R110 "CRCW0603300RJNEA" 0603 5525.62,3155.31 r270 top value=300
R111 "CRCW0603100RFKEA" 0603 2510.22,3155.31 r270 top value=100
R112 "CRCW0603100RFKEA" 0603 5447.66,3155.31 r270 top value=100
R113 "CRCW0603300RJNEA" 0603 2444.92,3155.31 r270 top value=300
R114 "CRCW0603300RJNEA" 0603 5385.36,3155.31 r270 top value=300
R115 "CRCW0603100RFKEA" 0603 2370.12,3155.31 r270 top value=100
R116 "CRCW0603100RFKEA" 0603 5310.56,3155.31 r270 top value=100
R117 "CRCW0603300RJNEA" 0603 2304.81,3155.31 r270 top value=300
R118 "CRCW0603300RJNEA" 0603 5247.07,3155.31 r270 top value=300
R119 "CRCW0603100RFKEA" 0603 2230.01,3155.31 r270 top value=100
R120 "CRCW120680R6FKEA" 1206 2127.3,3487.01 r270 top value=80.6
R121 "CRCW120680R6FKEA" 1206 5064.55,3487.99 r270 top value=80.6
R122 "CRCW120680R6FKEA" 1206 2127.3,3487.01 r270 bottom value=80.6
R123 "CRCW120680R6FKEA" 1206 5064.55,3487.99 r270 bottom value=80.6
R124 "CRCW120680R6FKEA" 1206 1987.8,3487.01 r270 top value=80.6
R125 "CRCW120680R6FKEA" 1206 4927.17,3487.99 r270 top value=80.6
R126 "CRCW120680R6FKEA" 1206 1987.8,3487.01 r270 bottom value=80.6
R127 "CRCW120680R6FKEA" 1206 4927.17,3487.99 r270 bottom value=80.6
R128 "CRCW120680R6FKEA" 1206 1849.05,3487.01 r270 top value=80.6
R129 "CRCW120680R6FKEA" 1206 4789.56,3487.99 r270 top value=80.6
R130 "CRCW120680R6FKEA" 1206 1849.05,3487.01 r270 bottom value=80.6
R131 "CRCW120680R6FKEA" 1206 4789.56,3487.99 r270 bottom value=80.6
R132 "CRCW120680R6FKEA" 1206 1706.98,3487.01 r270 top value=80.6
R133 "CRCW120680R6FKEA" 1206 4646.65,3487.99 r270 top value=80.6
R134 "CRCW120680R6FKEA" 1206 1706.98,3487.01 r270 bottom value=80.6
R135 "CRCW120680R6FKEA" 1206 4646.65,3487.99 r270 bottom value=80.6
R136 "CRCW120680R6FKEA" 1206 1566.87,3487.01 r270 top value=80.6
R137 "CRCW120680R6FKEA" 1206 4506.39,3487.99 r270 top value=80.6
R138 "CRCW120680R6FKEA" 1206 1566.87,3487.01 r270 bottom value=80.6
R139 "CRCW120680R6FKEA" 1206 4506.39,3487.99 r270 bottom value=80.6
R140 "CRCW120680R6FKEA" 1206 1426.48,3487.01 r270 top value=80.6
R141 "CRCW120680R6FKEA" 1206 4361.64,3487.99 r270 top value=80.6
R142 "CRCW120680R6FKEA" 1206 1426.48,3487.01 r270 bottom value=80.6
R143 "CRCW120680R6FKEA" 1206 4361.64,3487.99 r270 bottom value=80.6
R144 "CRCW120680R6FKEA" 1206 1286.65,3487.01 r270 top value=80.6
R145 "CRCW120680R6FKEA" 1206 4222.01,3487.99 r270 top value=80.6
R146 "CRCW120680R6FKEA" 1206 1286.65,3487.01 r270 bottom value=80.6
R147 "CRCW120680R6FKEA" 1206 4222.01,3487.99 r270 bottom value=80.6
R148 "CRCW120680R6FKEA" 1206 4085.18,3487.99 r270 top value=80.6
R149 "CRCW120680R6FKEA" 1206 1146.54,3487.01 r270 top value=80.6
R150 "CRCW120680R6FKEA" 1206 4085.18,3487.99 r270 bottom value=80.6
R151 "CRCW120680R6FKEA" 1206 1146.54,3487.01 r270 bottom value=80.6
R152 "CRCW06030000Z0EA" 0603 3720.47,3521.66 r0 top value=0
R153 "CRCW06030000Z0EA" 0603 3976.94,3374.55 r270 top value=0
R154 "CRCW0603100RFKEA" 0603 5170.3,3155.31 r270 top value=100
R155 "CRCW0603300RJNEA" 0603 2164.7,3155.31 r270 top value=300
R156 "CRCW0603300RJNEA" 0603 5104.84,3155.31 r270 top value=300
R157 "CRCW0603100RFKEA" 0603 2091.87,3155.31 r270 top value=100
R158 "CRCW0603100RFKEA" 0603 5030.53,3155.31 r270 top value=100
R159 "CRCW0603300RJNEA" 0603 2028.52,3155.31 r270 top value=300
R160 "CRCW0603300RJNEA" 0603 4967.52,3155.31 r270 top value=300
R161 "CRCW0603100RFKEA" 0603 1952.37,3155.31 r270 top value=100
R162 "CRCW0603100RFKEA" 0603 4887.68,3155.31 r270 top value=100
R163 "CRCW0603300RJNEA" 0603 1884.49,3155.31 r270 top value=300
R164 "CRCW0603300RJNEA" 0603 4824.31,3155.31 r270 top value=300
R165 "CRCW0603100RFKEA" 0603 1809.68,3155.31 r270 top value=100
R166 "CRCW0603100RFKEA" 0603 4749.51,3155.31 r270 top value=100
R167 "CRCW0603300RJNEA" 0603 1744.38,3155.31 r270 top value=300
R168 "CRCW0603300RJNEA" 0603 4684.05,3155.31 r270 top value=300
R169 "CRCW0603100RFKEA" 0603 1671.54,3155.31 r270 top value=100
R170 "CRCW0603100RFKEA" 0603 4609.25,3155.31 r270 top value=100
R171 "CRCW0603300RJNEA" 0603 1604.37,3155.31 r270 top value=300
R172 "CRCW0603300RJNEA" 0603 4543.79,3155.31 r270 top value=300
R173 "CRCW0603100RFKEA" 0603 1531.44,3155.31 r270 top value=100
R174 "CRCW0603100RFKEA" 0603 4468.98,3155.31 r270 top value=100
R175 "CRCW0603300RJNEA" 0603 1467.95,3155.31 r270 top value=300
R176 "CRCW0603300RJNEA" 0603 4403.52,3155.31 r270 top value=300
R177 "CRCW0603100RFKEA" 0603 1391.7,3155.31 r270 top value=100
R178 "CRCW0603100RFKEA" 0603 4326.82,3155.31 r270 top value=100
R179 "CRCW0603300RJNEA" 0603 1326.84,3155.31 r270 top value=300
R180 "CRCW0603300RJNEA" 0603 4263.26,3155.31 r270 top value=300
R181 "CRCW0603100RFKEA" 0603 1251.22,3155.31 r270 top value=100
R182 "CRCW0603100RFKEA" 0603 4192.14,3155.31 r270 top value=100
R183 "CRCW0603300RJNEA" 0603 1183.95,3155.31 r270 top value=300
R184 "CRCW0603300RJNEA" 0603 4123,3155.31 r270 top value=300
R185 "CRCW0603100RFKEA" 0603 1109.14,3155.31 r270 top value=100
R186 "CRCW0603100RFKEA" 0603 4045.79,3155.31 r270 top value=100
R187 "CRCW04020000Z0ED" 0603 565.71,226.16 r90 top value=0
R188 "CRCW060310K0FKEA" 0603 5525.62,2586.09 r90 top value=10.0k
R189 "CRCW060310K0FKEA" 0603 5505.92,2492.28 r0 top value=10.0k
R190 "RC0603JR-072KL" 0603 1549.1,2766.49 r0 bottom value=2.0k
R191 "CRCW04020000Z0ED" 0603 4858.98,2487.95 r0 top value=0
R192 "CRCW060310K0FKEA" 0603 1168.79,1257.08 r270 top value=10.0k
R193 "CRCW04020000Z0ED" 0603 1788.15,2400.05 r0 top value=0
R194 "CRCW04020000Z0ED" 0603 4992.76,2294.93 r270 top value=0
R195 "CRCW04020000Z0ED" 0603 5054.82,2275.15 r270 top value=0
R196 "CRCW04020000Z0ED" 0603 4956.51,2290.28 r270 bottom value=0
R197 "CRCW04020000Z0ED" 0603 5024.42,2290.28 r270 bottom value=0
R198 "CRCW0603100RFKEA" 0603 2586.94,2598.08 r90 top value=100
R199 "CRCW060310K0FKEA" 0603 2462.32,2493.85 r0 top value=10.0k
R200 "CRCW0603100RFKEA" 0603 2543.34,1965.4 r0 top value=100
R201 "CRCW1206154RFKEA" 1206 5783.88,2997.22 r180 bottom value=154
R202 "CRCW04020000Z0ED" 0603 1888.2,2296.92 r270 top value=0
R203 "RC1210FR-07220RL" 1210 1678,2900.63 r90 bottom value=220
R204 "CRCW04020000Z0ED" 0603 5250.04,2276.06 r270 top value=0
R205 "CRCW04020000Z0ED" 0603 5089.75,2275.57 r270 bottom value=0
R206 "CRCW04020000Z0ED" 0603 5158.31,2275.57 r270 bottom value=0
R207 "CRCW04020000Z0ED" 0603 5294.83,2275.57 r270 bottom value=0
R208 "CRCW04020000Z0ED" 0603 5231.34,2276.06 r270 bottom value=0
R209 "CRCW1206154RFKEA" 1206 5785.58,2893.07 r0 bottom value=154
R210 "CRCW04020000Z0ED" 0603 1893.88,2295.67 r270 bottom value=0
R211 "CRCW0603100RFKEA" 0603 5356.82,2275.57 r270 bottom value=100
R212 "CRCW04020000Z0ED" 0603 2167.49,2298.73 r270 top value=0
R213 "CRCW1206619RFKEA" 1206 2702.22,2616.93 r90 bottom value=619
R214 "CRCW1206619RFKEA" 1206 2810.49,2616.93 r90 bottom value=619
R215 "CRCW04020000Z0ED" 0603 2167.54,2297.38 r270 bottom value=0
R216 "CRCW0603499KFKEA" 0603 4763.02,2577.19 r0 bottom value=499k
R217 "CRCW04020000Z0ED" 0603 2303.73,2298.04 r270 top value=0
R218 "CRCW0603100RFKEA" 0603 2365.93,2298.04 r270 bottom value=100
R219 "RC0603FR-072ML" 0603 4769.07,2765.53 r0 bottom value=2.00Meg
R220 "RC0603FR-07300RL" 0603 4317.32,2503.94 r270 top value=300
R221 "CRCW060326K1FKEA" 0603 4931.35,2294.93 r270 top value=26.1k
R222 "CRCW04020000Z0ED" 0603 2234.19,2298.04 r270 top value=0
R223 "CRCW04020000Z0ED" 0603 2100.42,2297.38 r270 bottom value=0
R224 "CRCW04020000Z0ED" 0402 1357.13,2914.07 r270 bottom value=0
R225 "CRCW04020000Z0ED" 0603 2100.69,2298.73 r270 top value=0
R226 "CRCW04020000Z0ED" 0603 1958.92,2297 r270 bottom value=0
R227 "CRCW04020000Z0ED" 0603 1951.08,2296.57 r270 top value=0
R228 "CRCW060380K6FKEA" 0603 4379.66,2503.78 r90 top value=80.6k
R229 "CRCW060310M0JNEA" 0603 5423.07,2361.02 r270 bottom value=10Meg
R230 "CRCW0603200KFKEA" 0603 4444.07,2503.78 r270 top value=200k
R231 "CRCW0603200KFKEA" 0603 3379.16,2287.4 r0 top value=200k
R232 "CRCW0603150KFKEA" 0603 5313.53,2275.57 r90 top value=150k
R233 "RC0603FR-0733KL" 0603 3379.16,2218.34 r180 top value=33.0k
R234 "CRCW0603150KFKEA" 0603 3378.26,2435.04 r0 top value=150k
R235 "CRCW0603499KFKEA" 0603 1791.34,2562.99 r0 bottom value=499k
R236 "RC0603FR-07300RL" 0603 4307.77,2980.49 r270 bottom value=300
R237 "RC0603FR-07300RL" 0603 4181.58,2701.55 r270 bottom value=300
R238 "RT0603BRD0718KL" 0603 5859.78,4129.88 r0 bottom value=18.0k
R239 "CRCW0603100RFKEA" 0603 1695.4,2613.35 r0 top value=100
R240 "CRCW060380K6FKEA" 0603 4232.16,2980.49 r90 bottom value=80.6k
R241 "CRCW060380K6FKEA" 0603 4117.29,2701.91 r90 bottom value=80.6k
R242 "CRCW0603200KFKEA" 0603 4117.29,2899.61 r0 bottom value=200k
R243 "CRCW0603200KFKEA" 0603 4046.43,2564.11 r90 bottom value=200k
R244 "CRCW0603150KFKEA" 0603 4381.07,2840.55 r270 bottom value=150k
R245 "CRCW0603150KFKEA" 0603 4156.66,2377.1 r180 bottom value=150k
R246 "CRCW0603150KFKEA" 0603 4117.29,2845.39 r0 bottom value=150k
R247 "CRCW0603150KFKEA" 0603 3208.66,2454.72 r0 bottom value=150k
R248 "CRCW060310M0JNEA" 0603 2428.27,2422.39 r270 bottom value=10Meg
R249 "CRCW060310K0FKEA" 0603 3264.57,2174.77 r0 bottom value=10.0k
R250 "CRCW060310M0JNEA" 0603 3260.33,2235.43 r0 bottom value=10Meg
